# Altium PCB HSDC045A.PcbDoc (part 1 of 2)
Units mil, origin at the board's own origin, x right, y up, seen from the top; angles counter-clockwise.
Board outline 3400 x 2200 mil, 4 copper layers (Top Layer, GND, Power, Bottom Layer), stack 60.6 mil thick; 158 components, 100 nets, 469 pads, 343 vias.
Unrouted connection lines stored in the file: 20.
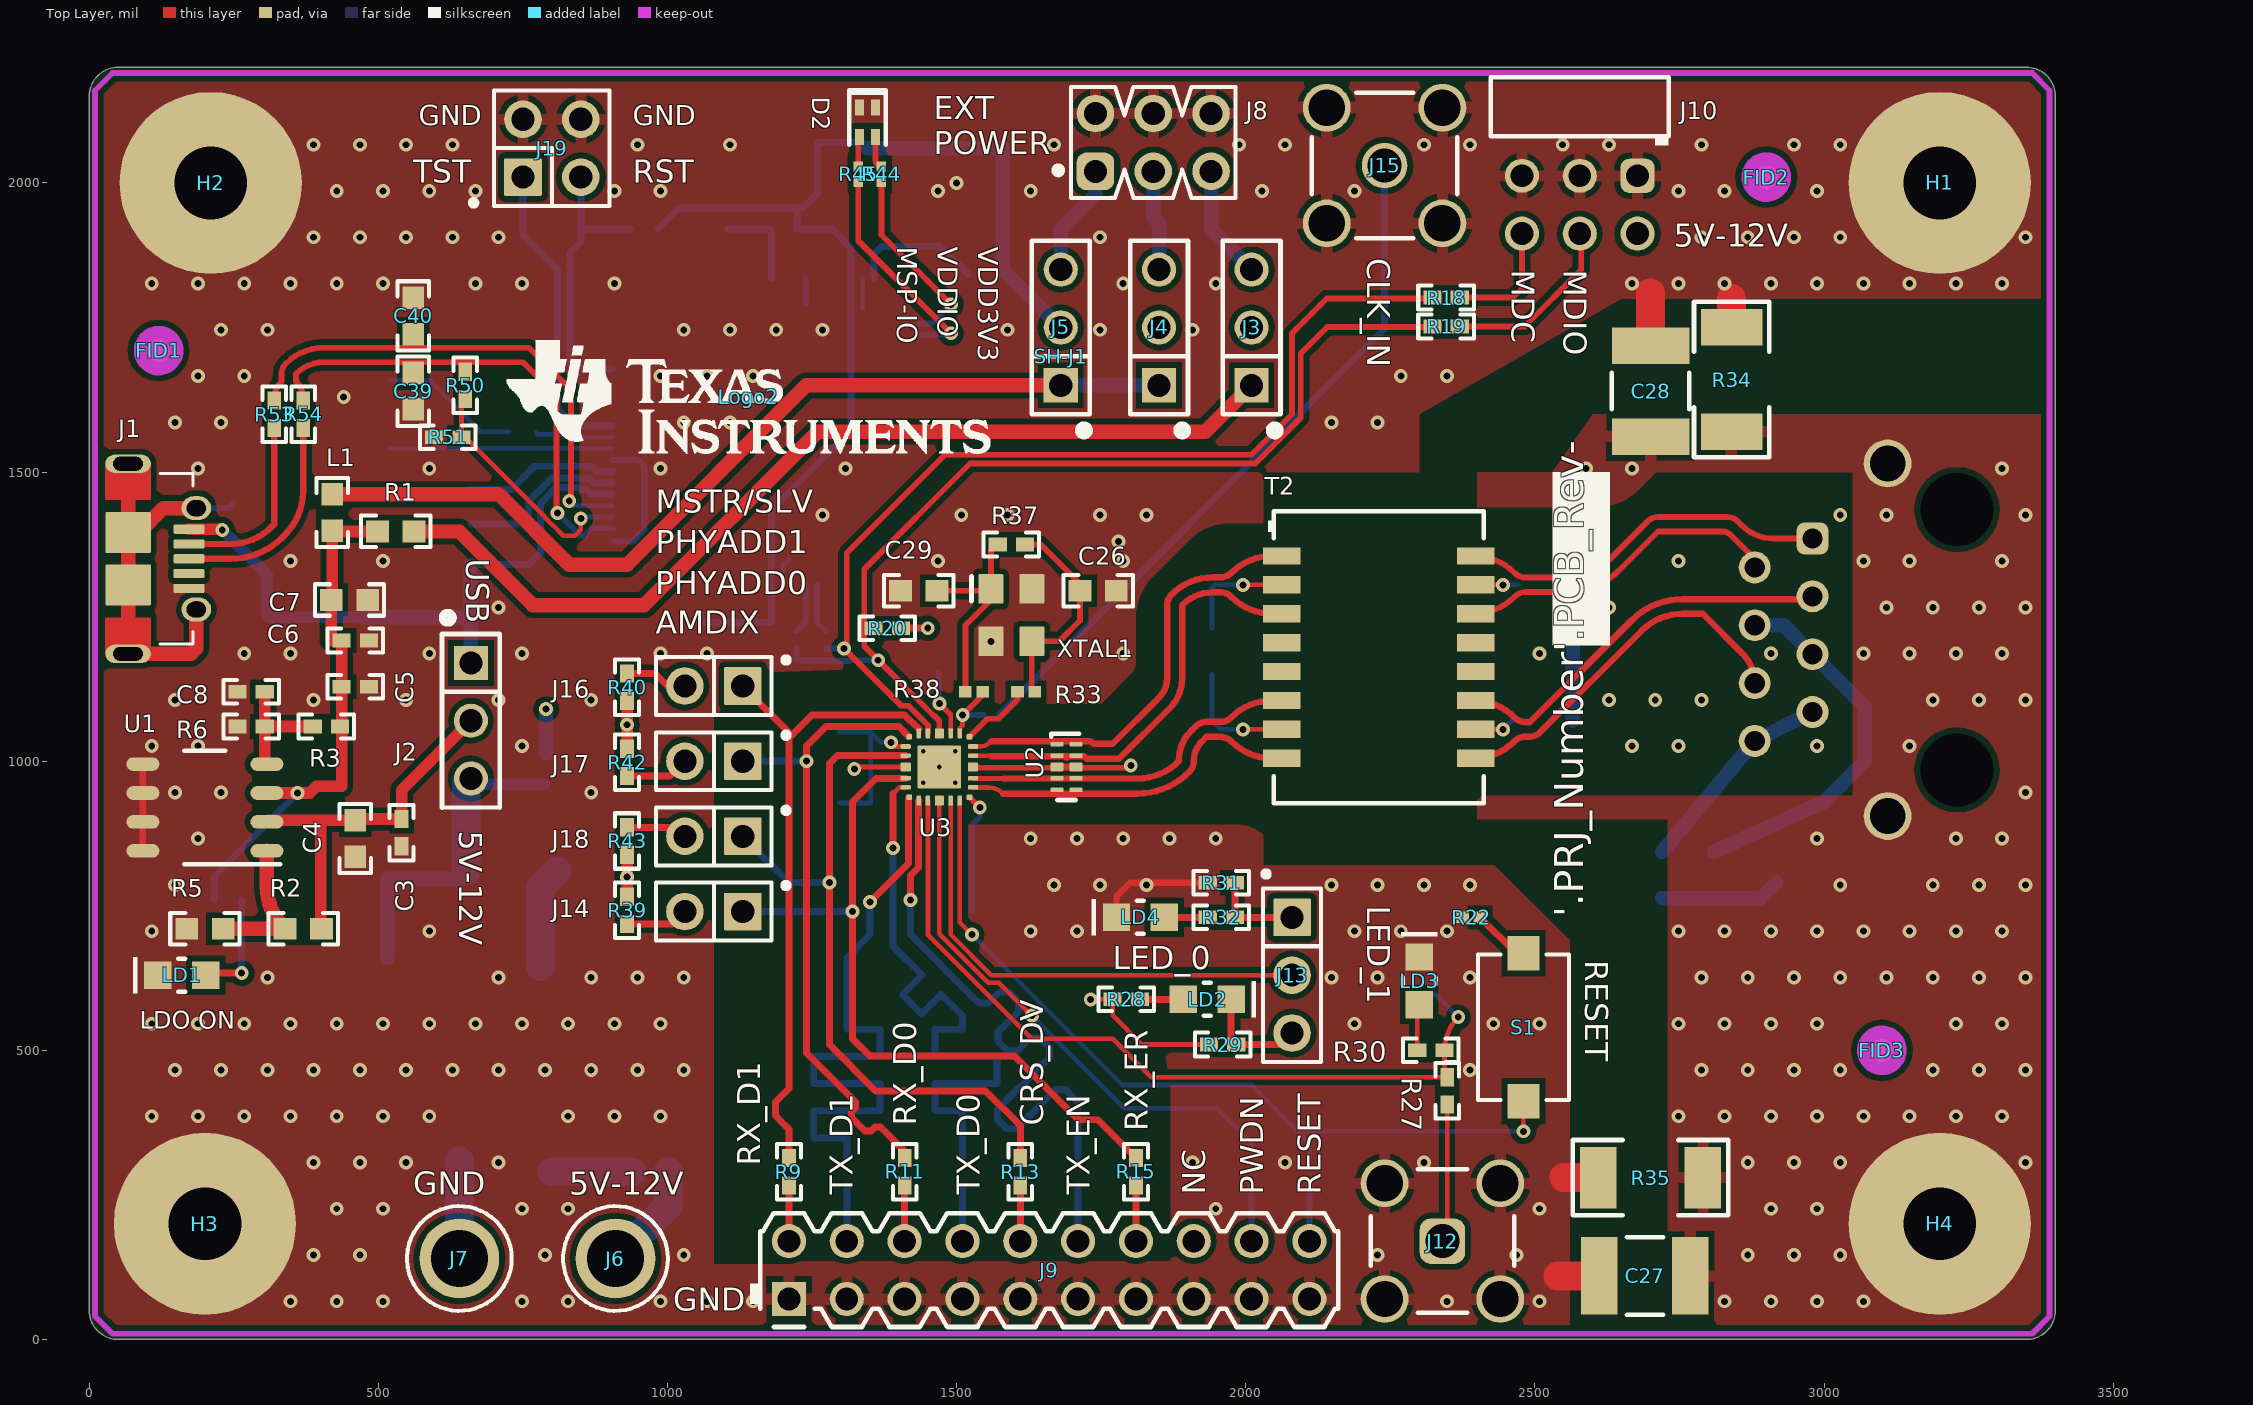
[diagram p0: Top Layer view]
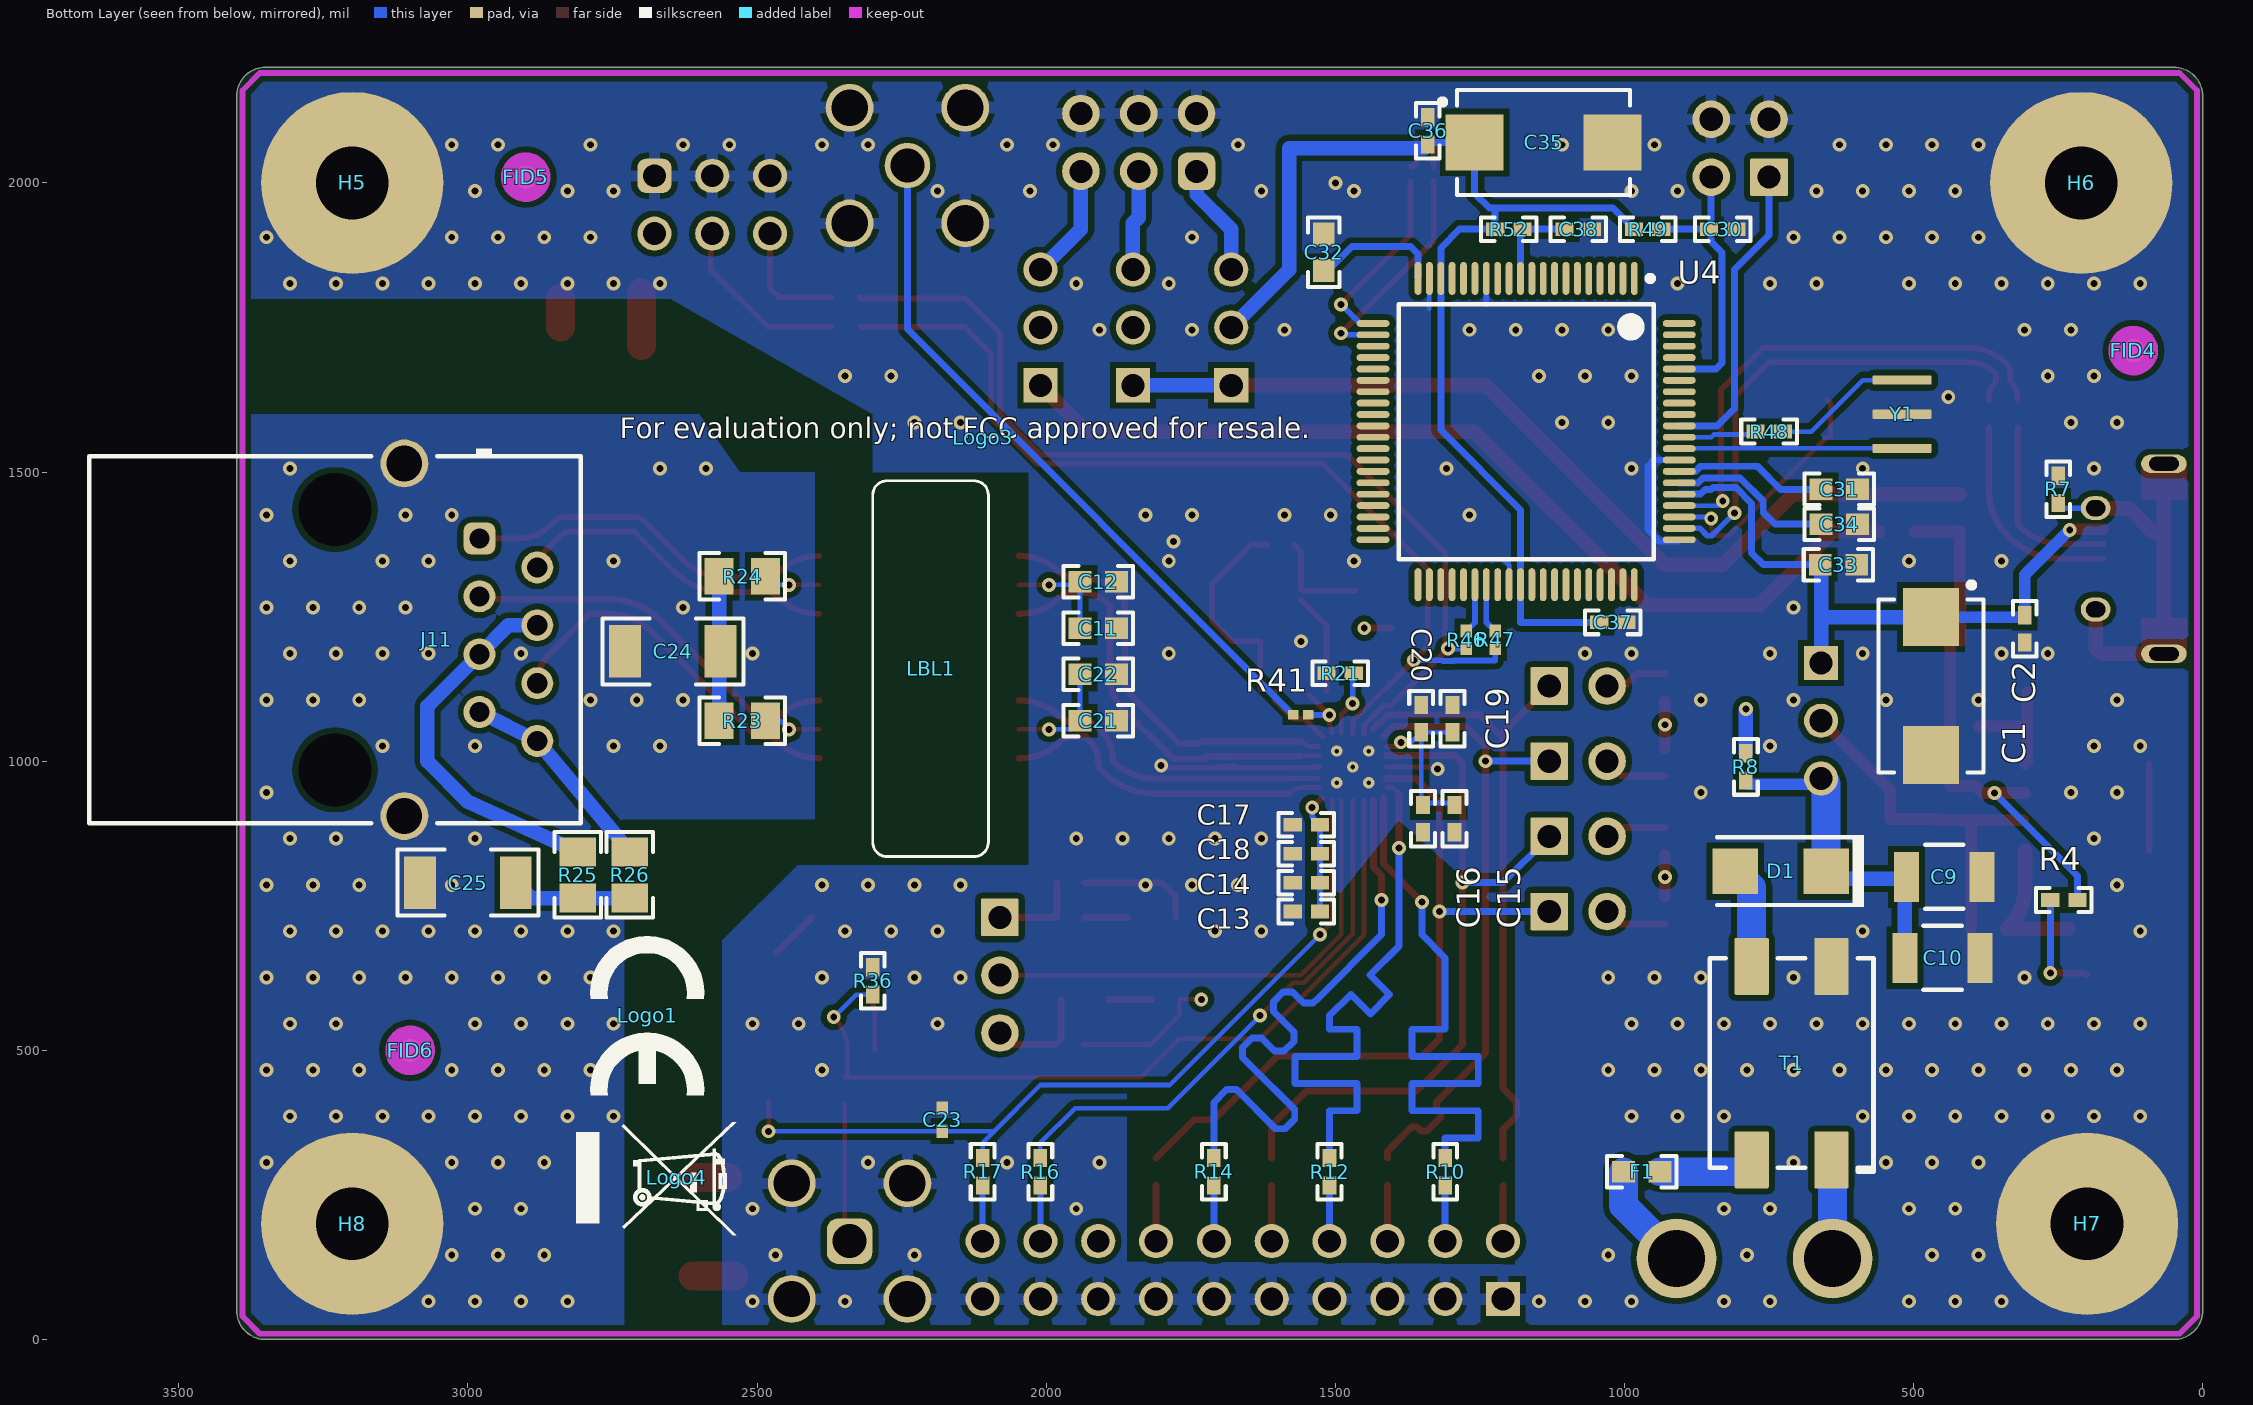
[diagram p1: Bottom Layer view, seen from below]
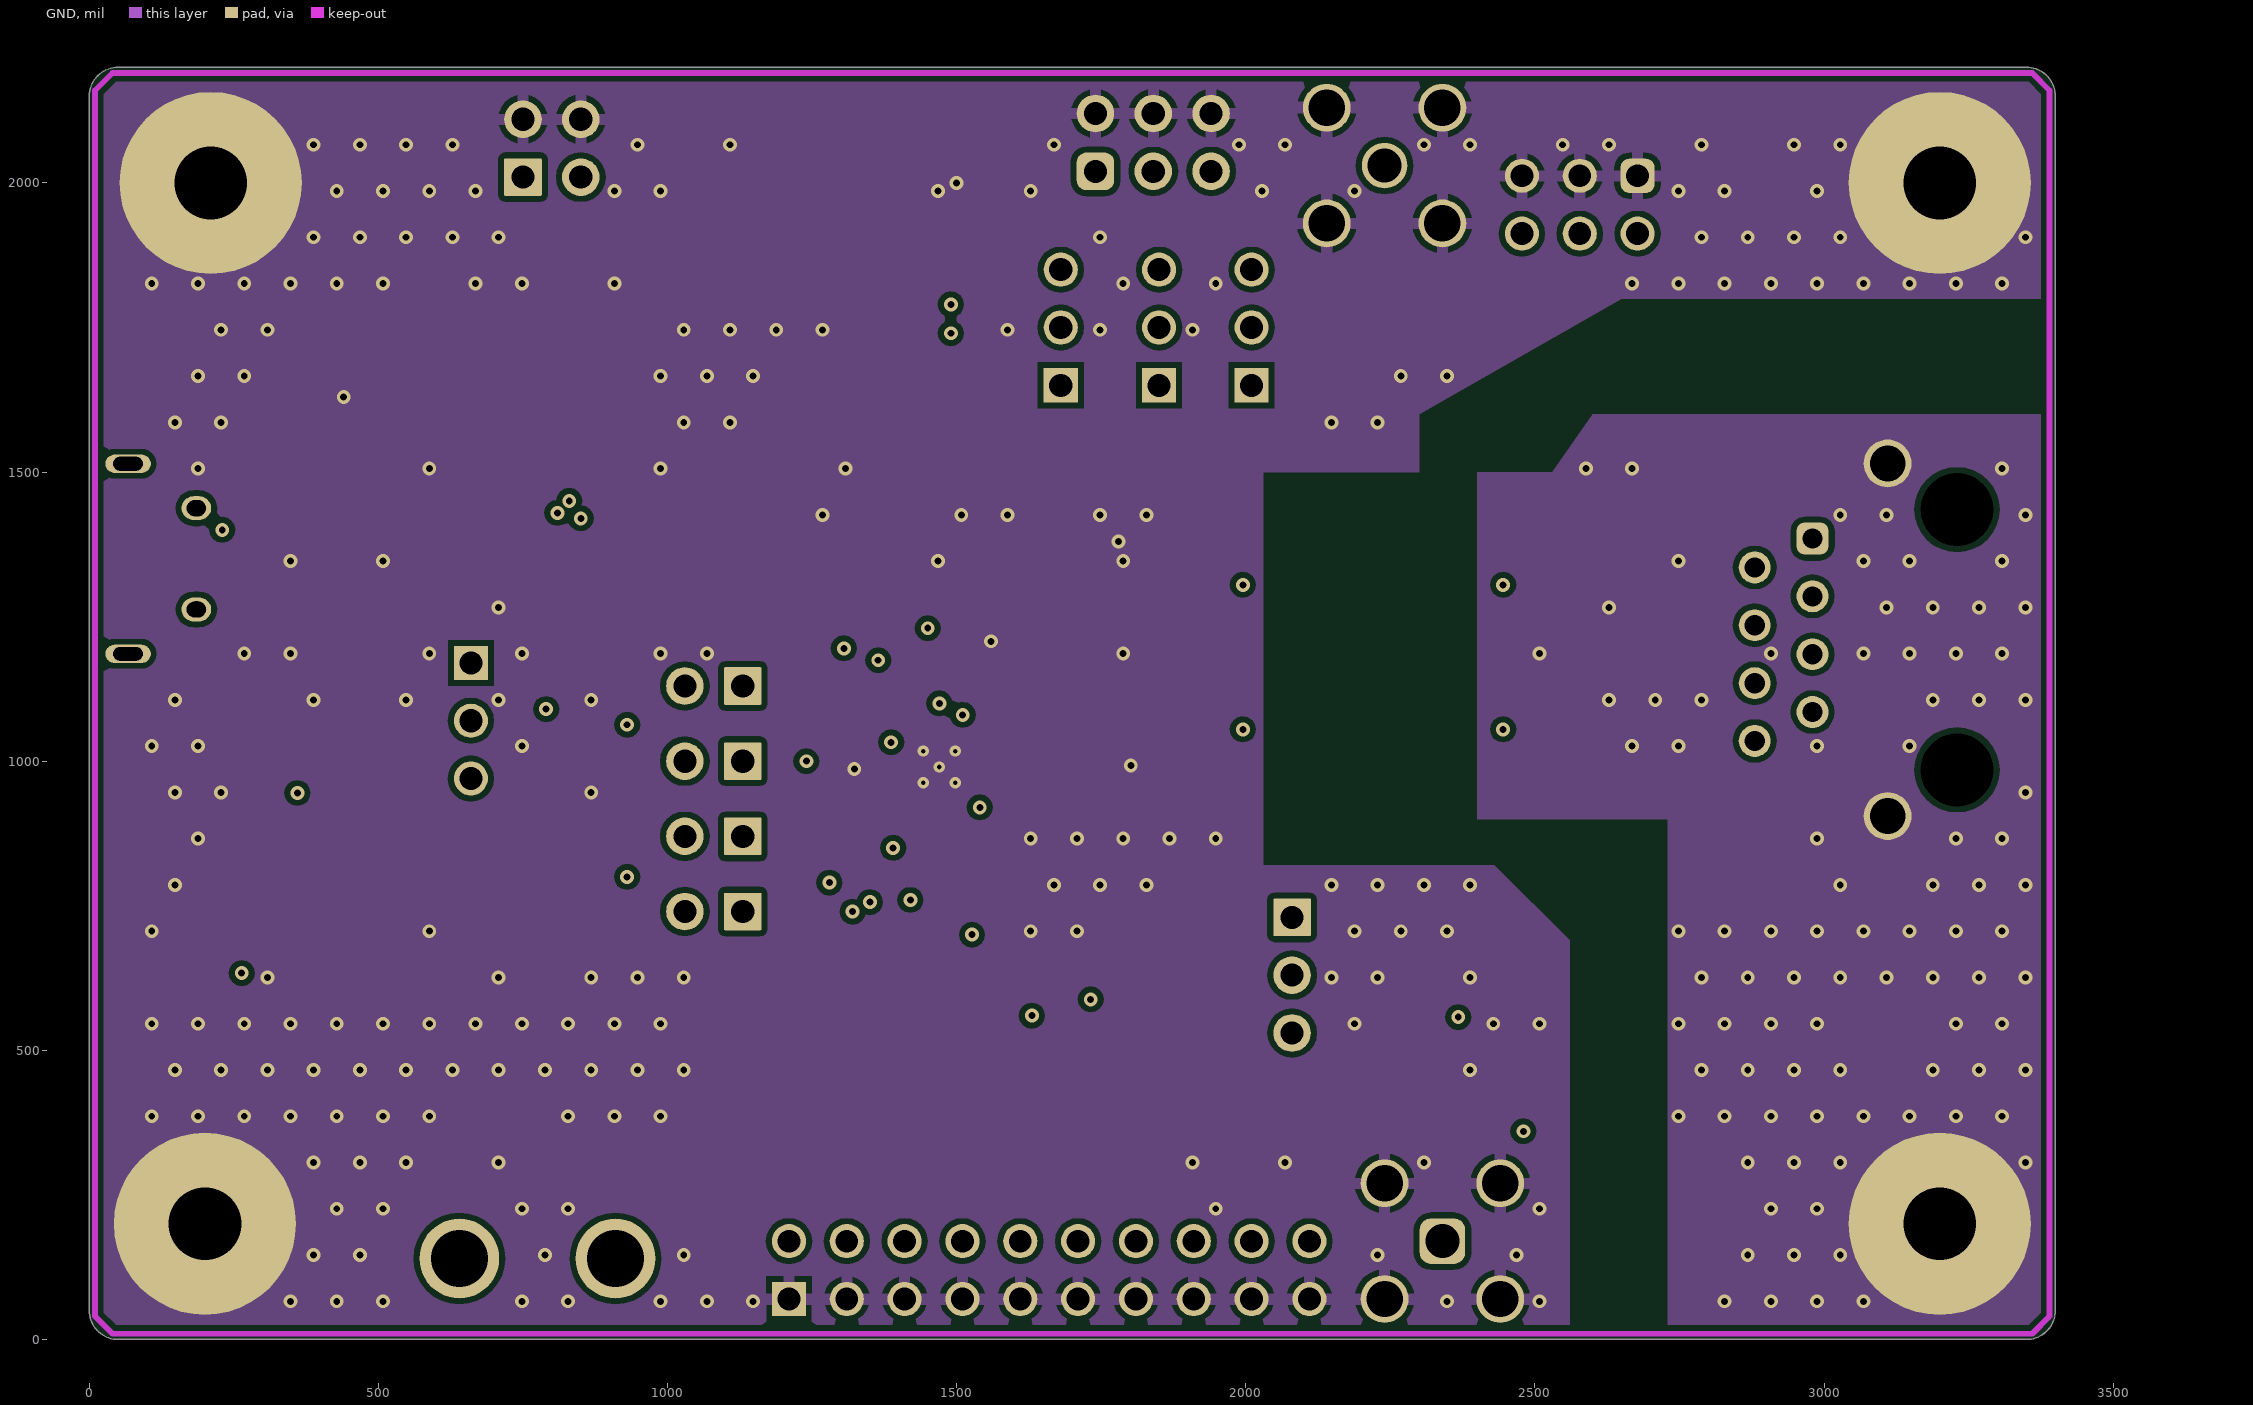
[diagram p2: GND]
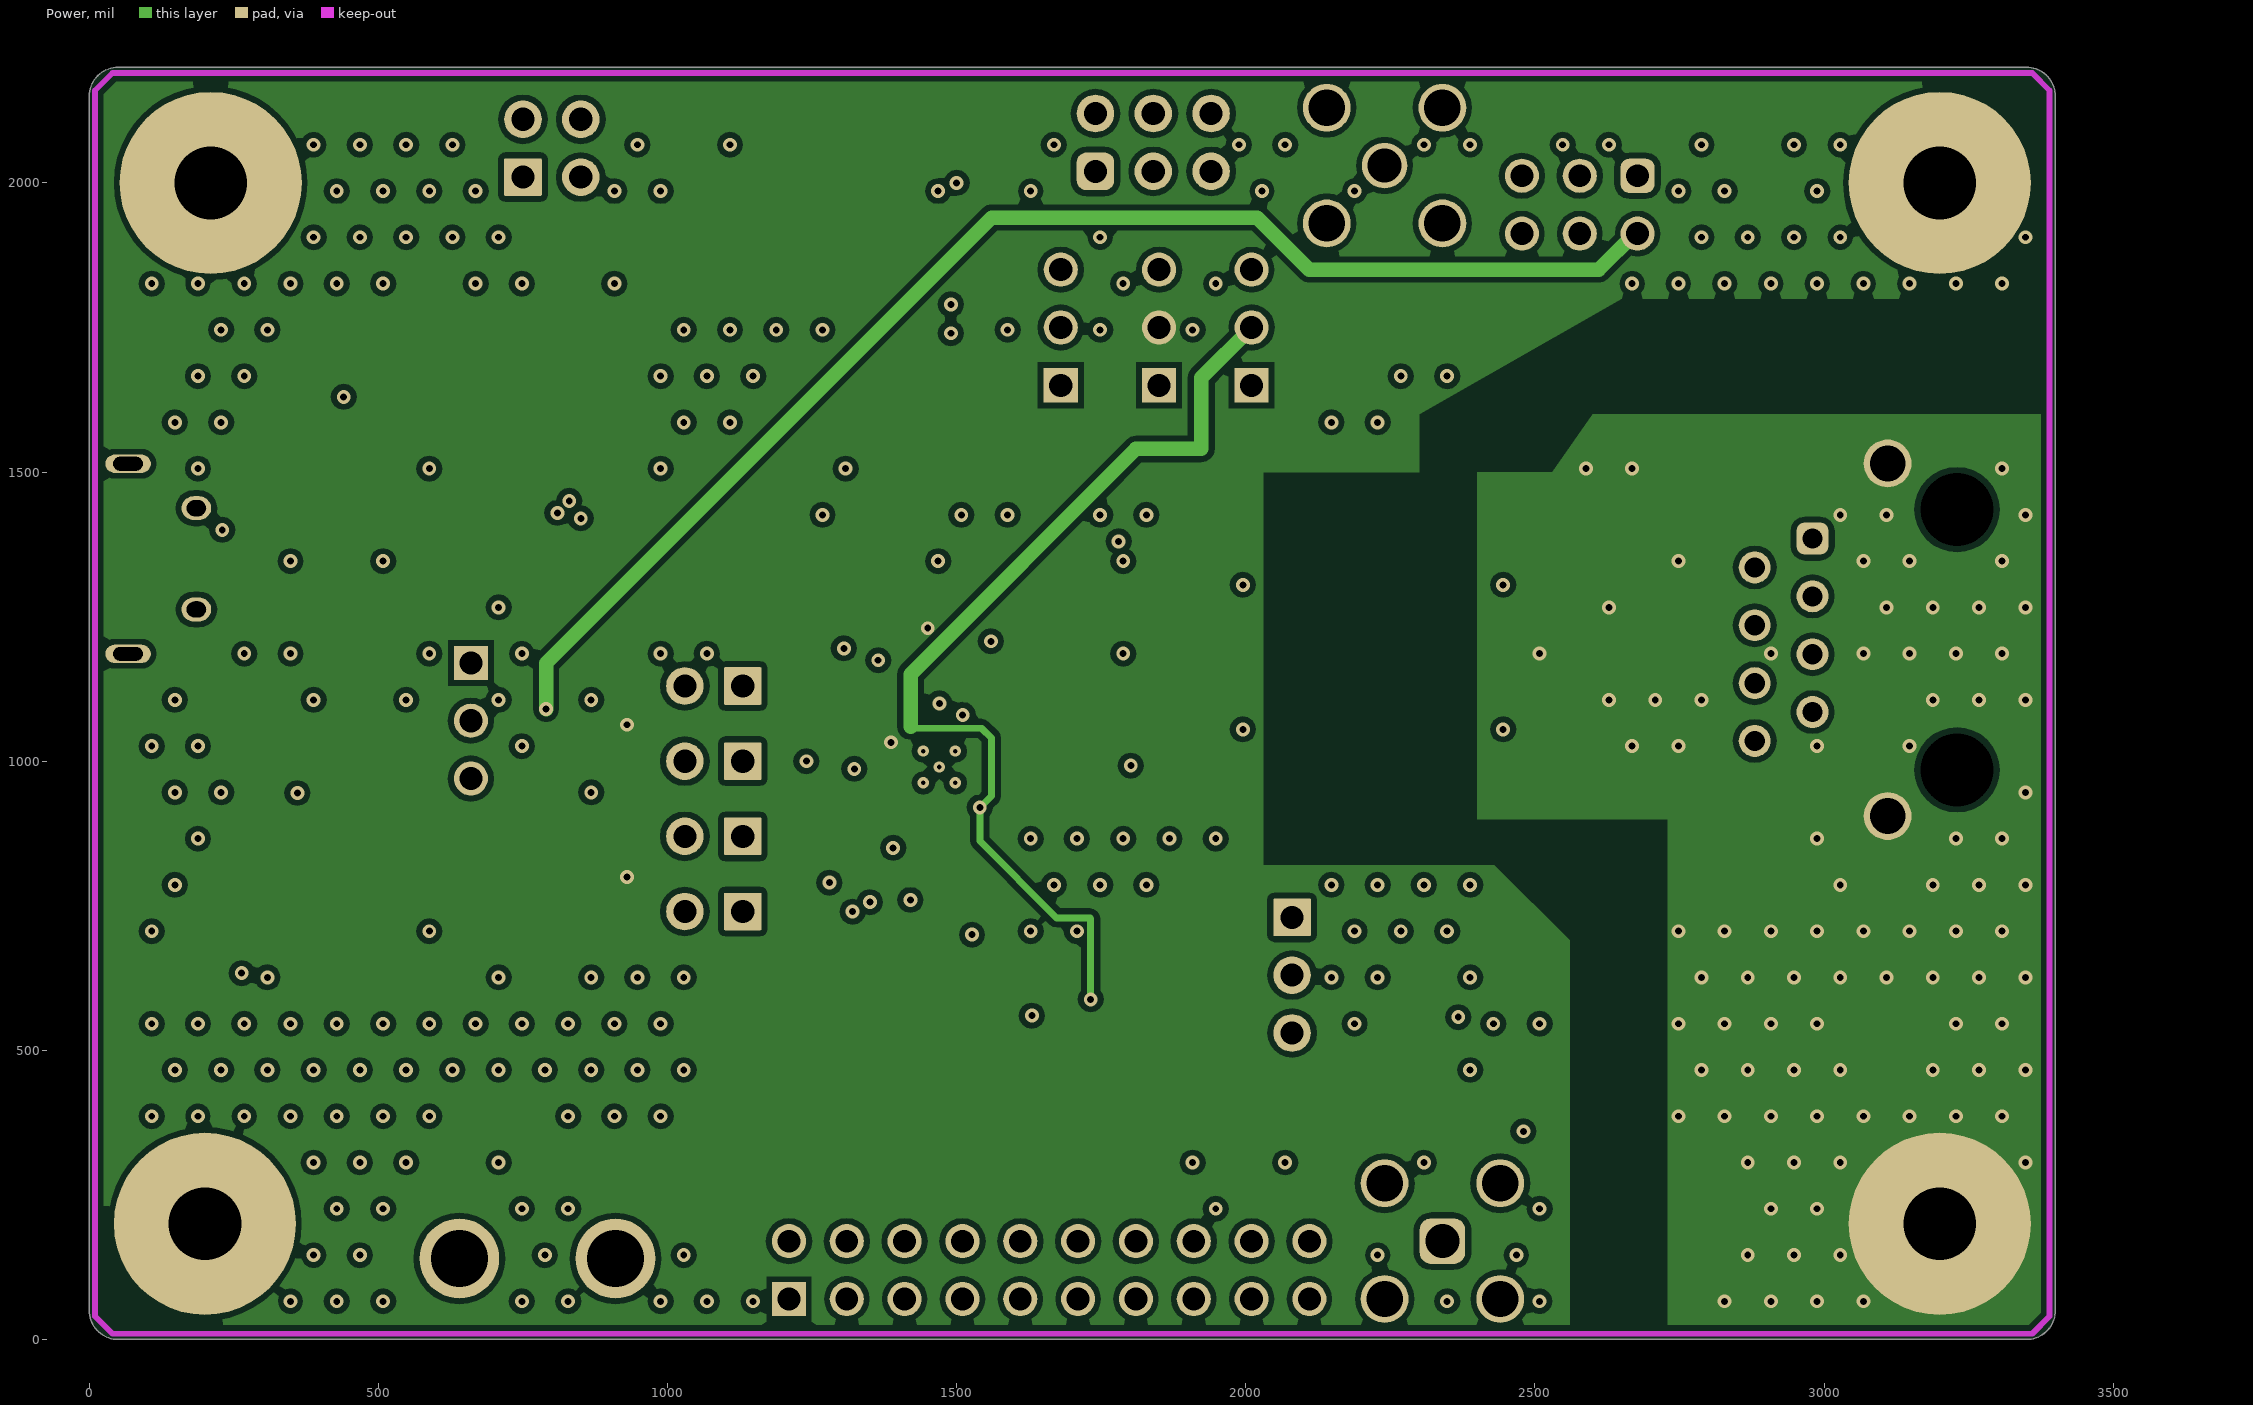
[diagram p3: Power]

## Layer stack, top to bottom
Top Solder: solder mask 0.4, Solder Resist, Dk 3.5
Top Layer: signal copper 1.4
Dielectric 1: prepreg 8, FR-4, Dk 4.6
GND: signal copper 1.4
Dielectric 2: core 39, FR-4, Dk 4.6
Power: signal copper 1.4
Dielectric 3: prepreg 8, FR-4, Dk 4.6
Bottom Layer: signal copper 1.4
Bottom Solder: solder mask 0.4, Solder Resist, Dk 3.5

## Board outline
50,0 3350,0 ccw(c3350,50) 3400,50 3400,2150 ccw(c3350,2150) 3350,2200 50,2200 ccw(c50,2150) 0,2150 0,50 ccw(c50,50)

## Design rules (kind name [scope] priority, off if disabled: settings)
AcuteAngle [All] p1: minimum=4.50000000000000E+0001 checktracksonly=FALSE
AssemblyTestPointUsage [All] p1: valid=2
BoardOutlineClearance BoardOutlineClearance_MountingHoles [OnCopper and InComponentClass('Mounting Holes')] p1: gap=14 ignorepadtopadclearanceinfootprint=FALSE
BoardOutlineClearance BoardOutlineClearance_Poly [OnCopper and IsPoly] p2: gap=14 ignorepadtopadclearanceinfootprint=FALSE
BoardOutlineClearance [OnCopper and Not InComponentClass('Logo') and not InComponentClass('FiducialMark') and not InRegion(1000,500,4000,800) and not InPoly] p3: gap=14 ignorepadtopadclearanceinfootprint=FALSE
Clearance "Stitching GND" [IsStitchingVia and InNet('GND') vs (IsVia and (Not IsStitchingVia)) Or (IsPad and (Not InComponent('U3')))] p1: gap=5 ignorepadtopadclearanceinfootprint=FALSE except(0: Arc-Hole Track-Hole SMDPad-Hole THPad-Hole Via-Hole Fill-Hole Poly-Hole Region-Hole Text-Hole)
Clearance Clearance_Keepouts [((IsTrack Or IsArc) And Not InPoly) And IsFree and IsKeepOut vs ((IsTrack Or IsArc) And Not InPoly) And IsFree and IsKeepOut] p2: gap=0 ignorepadtopadclearanceinfootprint=FALSE
Clearance Clearance_Poly [InPolygon] p3: gap=10 ignorepadtopadclearanceinfootprint=FALSE except(0: Arc-Hole Track-Hole SMDPad-Hole THPad-Hole Via-Hole Fill-Hole Poly-Hole Region-Hole Text-Hole)
Clearance Clearance_FiducialMark [IsKeepOut and InComponentClass('FiducialMark') vs IsPad and InComponentClass('FiducialMark')] p4: gap=0 ignorepadtopadclearanceinfootprint=FALSE
Clearance [All] p5: gap=5 ignorepadtopadclearanceinfootprint=FALSE
ComponentClearance ComponentClearance_MountingHoles_FiducialMarks [InComponentClass('Mounting Holes') vs InComponentClass('FiducialMark')] p1: gap=50 collisioncheckmode=3 verticalgap=10 showdistances=FALSE
ComponentClearance ComponentClearance_Shunt [InComponentClass('Header') vs InComponentClass('Shunt')] p2: gap=0 collisioncheckmode=3 verticalgap=0 showdistances=FALSE
ComponentClearance ComponentClearance_Shunt_1 [InComponentClass('Shunt') vs InComponentClass('Shunt')] p3: gap=0 collisioncheckmode=3 verticalgap=0 showdistances=FALSE
ComponentClearance ComponentClearance_Logo [InComponentClass('Logo')] p4: gap=50 collisioncheckmode=3 verticalgap=10 showdistances=FALSE
ComponentClearance ComponentClearance_ScrewToNut [(HasFootprint('NY PMS 440 0025 PH')) vs (HasFootprint('Keystone_1902C'))] p5: gap=5 collisioncheckmode=3 verticalgap=10 showdistances=FALSE
ComponentClearance ComponentClearance_MountingHoles [InComponentClass('Mounting Holes')] p6: gap=250 collisioncheckmode=3 verticalgap=100000 showdistances=FALSE
ComponentClearance ComponentClearance_SmallPassives [HasFootprint('0201*') or HasFootprint('0402*') or HasFootprint('0508') or HasFootprint('0603*') or HasFootprint('0612') or HasFootprint('0805*') or HasFootprint('0815*') or HasFootprint('0830*') or HasFootprint('1206*') or HasFootprint('1210*') or HasFootprint('1808*') or HasFootprint('1812*') or HasFootprint('1825*') or HasFootprint('2010*') or HasFootprint('2220*') or HasFootprint('2225*') or HasFootprint('2512*') or HasFootprint('2728*') or HasFootprint('3518*') vs HasFootprint('0201*') or HasFootprint('0402*') or HasFootprint('0508') or HasFootprint('0603*') or HasFootprint('0612') or HasFootprint('0805*') or HasFootprint('0815*') or HasFootprint('0830*') or HasFootprint('1206*') or HasFootprint('1210*') or HasFootprint('1808*') or HasFootprint('1812*') or HasFootprint('1825*') or HasFootprint('2010*') or HasFootprint('2220*') or HasFootprint('2225*') or HasFootprint('2512*') or HasFootprint('2728*') or HasFootprint('3518*')] p7: gap=14.96 collisioncheckmode=3 verticalgap=10 showdistances=FALSE
ComponentClearance ComponentClearance_THtoSMT [IsThruComponent vs IsSMTComponent] p8: gap=10 collisioncheckmode=3 verticalgap=30 showdistances=FALSE
ComponentClearance ComponentClearance_THtoTH [IsThruComponent vs IsThruComponent] p9: gap=30 collisioncheckmode=3 verticalgap=30 showdistances=FALSE
ComponentClearance [All] p10: gap=30 collisioncheckmode=3 verticalgap=10 showdistances=FALSE
DiffPairsRouting [All] p1: maxlimit=16 minlimit=3 mostfreqgap=15 toplayer_minwidth=3 toplayer_maxwidth=11 toplayer_prefwidth=9 midlayer1_minwidth=3 midlayer1_maxwidth=11 midlayer1_prefwidth=9 midlayer2_minwidth=3 midlayer2_maxwidth=11 midlayer2_prefwidth=9 bottomlayer_minwidth=3 bottomlayer_maxwidth=11 bottomlayer_prefwidth=9 maxuncoupledlength=1000
FabricationTestPointUsage TestPointUsage [All] p1: valid=2 allowmultiple=FALSE
FabricationTestpoint Testpoint [All] p1: side=3 testpointundercomponent=TRUE minsize=40 maxsize=100 preferedsize=60 minholesize=0 maxholesize=40 preferedholesize=32 testpointgrid=1 allowsidetop=TRUE allowsidebottom=TRUE usegrid=TRUE gridtolerance=0.01
FanoutControl Fanout_LCC [IsLCC] p1: bgadir=Out bgaviamode=Centered fanoutstyle=Auto fanoutdirection=Alternating viagrid=1 // Fanout_LCC (Default Rule)
FanoutControl Fanout_BGA [IsBGA] p2: bgadir=Out bgaviamode=Centered fanoutstyle=Auto fanoutdirection=Alternating viagrid=1 // Fanout_BGA (Default Rule)
FanoutControl Fanout_Default [All] p4: bgadir=Out bgaviamode=Centered fanoutstyle=Auto fanoutdirection=Alternating viagrid=1 // Fanout_Default (Default Rule)
FanoutControl Fanout_Small [(CompPinCount < 5)] p5: bgadir=Out bgaviamode=Centered fanoutstyle=Auto fanoutdirection=OutThenIn viagrid=1 // Fanout_Small (Default Rule)
HoleSize [All] p1: absolutevalues=TRUE maxlimit=300 minlimit=6 maxpercent=80.000 minpercent=20.000
MinimumAnnularRing MinimumAnnularRing_ThermalPadVias [IsVia and InAnyComponent] p1: minimumring=5.91
MinimumAnnularRing MinimumAnnularRing_J1 [InNet('NetJ1_6')] p2: minimumring=2
MinimumAnnularRing [All] p3: minimumring=5
MinimumSolderMaskSliver MinimumSolderMaskSliver_Logo [InComponentClass('Logo') vs InComponentClass('Logo')] p1: minsoldermaskwidth=0.7
MinimumSolderMaskSliver [All] p2: minsoldermaskwidth=3.94
PlaneConnect [All] p1: planeconnectstyle=Direct reliefexpansion=10 reliefentries=4 reliefconductorwidth=10 reliefairgap=10
PolygonConnect PolygonConnect_ThermalRelief [InComponent('J9') or InComponent('J12')or InComponent('J15')or InComponent('R34')or InComponent('C28')or InComponent('R35')or InComponent('C27')or InComponent('J8')or InComponent('J10') or InComponent('J19') vs InNet('GND')or InNet('EARTH_GND')] p1: connectstyle=Relief reliefconductorwidth=20 reliefentries=4 polygonreliefangle="90 Angle" airgapwidth=10
PolygonConnect [All] p2: connectstyle=Direct reliefconductorwidth=20 reliefentries=4 polygonreliefangle="90 Angle" airgapwidth=10
RoutingVias ThermalPadVias [IsVia and InAnyComponent] p1: holewidth=7.87 width=19.68 viastyle="Through Hole" minholewidth=7.87 minwidth=19.68 maxholewidth=12.99 maxwidth=23.62
RoutingVias [All] p2: holewidth=12 width=24 viastyle="Through Hole" minholewidth=6 minwidth=12 maxholewidth=40 maxwidth=65
SilkToBoardRegionClearance [Not ((IsComment or IsDesignator) And (Hide <> 'False')) and not InRegion(1000,500,4000,800)] p1:
SilkToSilkClearance SilkToSilkClearance_Pb-FreeLogo [(HasFootprint('Pb-Free_Overlay_Medium') OR HasFootprint('Pb-Free_Overlay_Small')) vs (HasFootprint('Pb-Free_Overlay_Medium') OR HasFootprint('Pb-Free_Overlay_Small'))] p1: silktosilkclearance=0
SilkToSilkClearance [All] p2: silktosilkclearance=4
SilkToSolderMaskClearance SilkToComponentPadClearance [IsPad and InAnycomponent] p1: minsilkscreentomaskgap=4 clearancetoexposedcopper=TRUE
SilkToSolderMaskClearance "Silk to Solder Mask Opening" [All] p2: minsilkscreentomaskgap=4 clearancetoexposedcopper=FALSE
SolderMaskExpansion [All] p1: expansion=1.97
Width Width_U3Pad [IsComponent = 'U3'] p1: maxlimit=50 minlimit=7 preferedwidth=12
Width [All] p2: maxlimit=100 minlimit=7 preferedwidth=12 checkconnectedcopper=TRUE
15 further rules are at their usual default settings.

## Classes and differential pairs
component class "Mounting Holes": H1 H2 H3 H4
component class Logo: Logo2
component class HSDC045A_Hardware: FID1 FID2 FID3 FID4 FID5 FID6 H1 H2 H3 H4 H5 H6 H7 H8 LBL1 Logo1 Logo2 Logo3 Logo4 SH-J1 SH-J2 SH-J3 SH-J4 SH-J5 ZZ1 ZZ2 ZZ3 ZZ4
component class FiducialMark: FID1 FID2 FID3 FID4 FID5 FID6
component class AssemblyNote: ZZ1 ZZ2 ZZ3 ZZ4
component class Label: LBL1
component class Header: J2 J3 J4 J5 J8 J9 J10 J13 J14 J16 J17 J18 J19 J22
component class HSDC045A_Coms: C30 C31 C32 C33 C34 C35 C36 C37 C38 C39 C40 D2 J19 R44 R45 R46 R47 R48 R49 R50 R51 R52 R53 R54 R56 U4 Y1
component class HSDC045A_DP83825: C11 C12 C13 C14 C15 C16 C17 C18 C19 C20 C21 C22 C23 C24 C25 C26 C27 C28 C29 J9 J10 J11 J12 J13 J14 J15 J16 J17 J18 LD2 LD3 LD4 R9 R10 R11 R12 R13 R14 R15 R16 R17 R18 R19 R20 R21 R22 R23 R24 R25 R26 R27 R28 R29 R30 R31 R32 R33 R34 R35 R36 R37 R38 R39 R40 R41 R42 R43 S1 T2 U2 U3 XTAL1
component class HSDC045A_Power: C1 C2 C3 C4 C5 C6 C7 C8 C9 C10 D1 F1 J1 J2 J3 J4 J5 J6 J7 J8 L1 LD1 R1 R2 R3 R4 R5 R6 R7 R8 T1 U1
differential pair RD: +RD_P -RD_N
differential pair TARGET_D: +TARGET_D_P -TARGET_D_N
differential pair TD_CH1: +TD_CH1_P -TD_CH1_N
differential pair TD_CH2: +TD_CH2_P -TD_CH2_N
differential pair TD: +TD_P -TD_N
differential pair USB: +USB_P -USB_N

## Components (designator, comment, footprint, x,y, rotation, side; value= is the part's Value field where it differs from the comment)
C1 "293D475X9035D2TE3" 7343-31 470,1130 r270 bottom value=4.7uF
C2 "GRM155R71C104KA88D" 0402 307.6,1228.82 r90 bottom value=0.1uF
C3 "GRM155R6YA105ME11D" 0402 540,876.38 r270 top value=1uF
C4 "GRM188R6YA106MA73" 0603 460,866.38 r270 top value=10uF
C5 "GRM155C81C225KE11D" 0402 460,1128.7 r0 top value=2.2uF
C6 "GRM155C81C225KE11D" 0402 460,1208.7 r0 top value=2.2uF
C7 "GRM188R6YA106MA73" 0603 450,1278.7 r0 top value=10uF
C8 "GRM1555C1E471JA01D" 0402 280,1120 r180 top value=470pF
C9 "CGA6P1X7R1C226M250AC" 1210_280 447.01,800 r180 bottom value=22uF
C10 "CGA6P1X7R1E106M250AC" 1210_280 450,660 r180 bottom value=10uF
C11 "C0603C104K8RACTU" 0603 1910,1230.06 r180 bottom value=0.1uF
C12 "C0603C104K8RACTU" 0603 1910,1310.09 r180 bottom value=0.1uF
C13 "C1005X5R1A104K050BA" 0402 1550,740 r0 bottom value=0.1uF
C14 "GRM155R60J106ME11" 0402 1550,790 r0 bottom value=10uF
C15 "C1005X5R1A104K050BA" 0402 1293.95,900.79 r270 bottom value=0.1uF
C16 "GRM155R60J106ME11" 0402 1348.35,900.79 r270 bottom value=10uF
C17 "GRM155R61A105KE15D" 0402 1550,890 r0 bottom value=1uF
C18 "GRM155R61A105KE15D" 0402 1550,840 r0 bottom value=1uF
C19 "GRM155R61A105KE15D" 0402 1297.26,1073.62 r90 bottom value=1uF
C20 "GRM155R61A105KE15D" 0402 1351.65,1073.62 r90 bottom value=1uF
C21 "C0603C104K8RACTU" 0603 1910,1070 r180 bottom value=0.1uF
C22 "C0603C104K8RACTU" 0603 1910,1150.03 r180 bottom value=0.1uF
C23 "GRM155R71H103KA88D" 0402L 2180,380 r270 bottom value=0.01uF
C24 "GR442QR73D102KW01L" 1808 2645.59,1190 r0 bottom value=1000pF
C25 "GR442QR73D102KW01L" 1808 3000,790 r0 bottom value=1000pF
C26 "CGA3E2C0G1H220J080AA" 0603 1744.57,1294.66 r0 top value=22pF
C27 "1812GC472KAT1A" 1812_254 2690,110 r0 top value=4700pF
C28 "1812GC472KAT1A" 1812_254 2700,1640 r270 top value=4700pF
C29 "CGA3E2C0G1H220J080AA" 0603 1434.57,1294.72 r180 top value=22pF
C30 "C1005NP01H102J050BA" 0402 830,1920 r0 bottom value=1000pF
C31 "C1608X5R1H224K080AB" 0603 628.5,1470 r180 bottom value=0.22uF
C32 "C1608X6S1H474K080AB" 0603 1520,1880 r90 bottom value=0.47uF
C33 "C1608X5R1V475K080AC" 0603 630,1340 r0 bottom value=4.7uF
C34 "C1608X5R1H224K080AB" 0603 628.5,1410 r180 bottom value=0.22uF
C35 "TPSD106K035R0125" 7343-31 1140,2070 r180 bottom value=10uF
C36 "GRM155R71C104KA88D" 0402 1340,2090 r270 bottom value=0.1uF
C37 "GRM155R71C104KA88D" 0402 1020,1240 r0 bottom value=0.1uF
C38 "GRM155R71C104KA88D" 0402 1080,1920 r0 bottom value=0.1uF
C39 "CGA3E2NP01H100D080AA" 0603 560,1640 r90 top value=10pF
C40 "CGA3E2NP01H100D080AA" 0603 560,1770 r270 top value=10pF
D1 "NRVBA160T3G" SMA 730,810 r0 bottom value=60V
D2 "HSMF-C165" HSMF-C165_RG 1346.06,2105.15 r90 top value=Rg
F1 "F0603E3R00FSTR" 0603 970,290 r180 bottom
FID1 "Fiducial" Fiducial10-20 120,1710 r0 top
FID2 "Fiducial" Fiducial10-20 2900,2010 r0 top
FID3 "Fiducial" Fiducial10-20 3100,500 r0 top
FID4 "Fiducial" Fiducial10-20 120,1710 r180 bottom
FID5 "Fiducial" Fiducial10-20 2900,2010 r180 bottom
FID6 "Fiducial" Fiducial10-20 3100,500 r180 bottom
H1 "NY PMS 440 0025 PH" "NY PMS 440 0025 PH" 3200,2000 r0 top locked
H2 "NY PMS 440 0025 PH" "NY PMS 440 0025 PH" 210,2000 r0 top locked
H3 "NY PMS 440 0025 PH" "NY PMS 440 0025 PH" 200,200 r0 top locked
H4 "NY PMS 440 0025 PH" "NY PMS 440 0025 PH" 3200,200 r0 top locked
H5 "1902C" Keystone_1902C 3200,2000 r180 bottom locked
H6 "1902C" Keystone_1902C 210,2000 r180 bottom locked
H7 "1902C" Keystone_1902C 200,200 r180 bottom locked
H8 "1902C" Keystone_1902C 3200,200 r180 bottom locked
J1 "475890001" Molex_0475890001 10,1350 r270 top
J2 "PEC03SAAN" CONN_PEC03SAAN 660,1070 r270 top
J3 "PEC03SAAN" CONN_PEC03SAAN 2010,1750 r90 top
J4 "PEC03SAAN" CONN_PEC03SAAN 1850,1750 r90 top
J5 "PEC03SAAN" CONN_PEC03SAAN 1680,1750 r90 top
J6 "1502-2" Keystone1502-2 910,140 r270 top
J7 "1502-2" Keystone1502-2 640,140 r270 top
J8 "5-146254-3" TE_5-146254-3 1840,2070 r0 top
J9 "PRPC010DAAN-RC" Sullins_xxxC010DAAN 1660,120 r90 top
J10 "90122-0763" Molex_90122-0763 2577.5,1962.31 r270 top
J11 "SS-7188S-A-NF" Stewart_SS-7188S-A-NF 3230,1210 r270 bottom
J12 "5-1814400-1" TE_5-1814400-1 2340,170 r90 top
J13 "HTSW-103-07-G-S" Samtec_HTSW-103-07-G-S 2080,630 r270 top
J14 "HTSW-102-07-G-S" Samtec_HTSW-102-07-G-S 1080,740 r180 top
J15 "5-1814832-1" TE_5-1814832-1 2240,2030 r270 top
J16 "HTSW-102-07-G-S" Samtec_HTSW-102-07-G-S 1080,1130 r180 top
J17 "HTSW-102-07-G-S" Samtec_HTSW-102-07-G-S 1080,1000 r180 top
J18 "HTSW-102-07-G-S" Samtec_HTSW-102-07-G-S 1080,870 r180 top
J19 "TSW-102-07-G-D" TSW-102-07-G-D 800,2060 r0 top
L1 "BLM18AG102SN1D" 0603 420,1430 r90 top value="1000 ohm"
LBL1 "THT-14-423-10" Label_650x200 2200,1160 r270 bottom
LD1 "QTLP630C4TR" QTLP630C_Green 160,630 r180 top value=Green
LD2 "QTLP630C4TR" QTLP630C_Green 1933.33,588.22 r0 top value=Green
LD3 "QTLP630C4TR" QTLP630C_Green 2300,620 r90 top value=Green
LD4 "QTLP630C4TR" QTLP630C_Green 1817.72,730 r180 top value=Green
Logo1 "CE Mark" CE_Mark_5mm 2690,560 r270 bottom
Logo2 "Texas Instruments" TI_Stacked_Overlay_Small 1140,1630 r0 top
Logo3 "FCC disclaimer" FCC_disclaimer 2110,1560 r180 bottom
Logo4 "WEEE logo" WEEE_Minimum 2640,280 r270 bottom
R1 "ERJ-3GEY0R00V" 0603 530,1397.22 r0 top value=0
R2 "ERJ-3GEY0R00V" 0603 370,710 r0 top value=0
R3 "CRCW0402100KDHEDP" 0402 410,1060 r0 top value=100k
R4 "CRCW0402470RJNED" 0402 240,760 r180 bottom value=470
R5 "ERJ-3GEY0R00V" 0603 200,710 r0 top value=0
R6 "CRCW0402165KFKED" 0402 280,1060 r0 top value=165k
R7 "CRCW040233R0JNED" 0402 250,1470 r90 bottom value=33
R8 "MCR01MZPJ000" 0402 790,990 r270 bottom value=0
R9 "CRCW04020000Z0ED" 0402 1210,290 r90 top value=0
R10 "CRCW04020000Z0ED" 0402 1310,290 r90 bottom value=0
R11 "CRCW04020000Z0ED" 0402 1410,290 r90 top value=0
R12 "CRCW04020000Z0ED" 0402 1510,290 r90 bottom value=0
R13 "CRCW04020000Z0ED" 0402 1610,290 r90 top value=0
R14 "CRCW04020000Z0ED" 0402 1710,290 r90 bottom value=0
R15 "CRCW04020000Z0ED" 0402 1810,290 r90 top value=0
R16 "CRCW04020000Z0ED" 0402 2010,290 r90 bottom value=0
R17 "CRCW04020000Z0ED" 0402 2110,290 r90 bottom value=0
R18 "CRCW04020000Z0ED" 0402 2346.22,1801.81 r0 top value=0
R19 "CRCW04020000Z0ED" 0402 2346.22,1751.81 r0 top value=0
R20 "CRCW04022K20JNED" 0402 1380,1230 r0 top value=2.2k
R21 "CRCW04026K49FKED" 0402 1491.81,1152.13 r0 bottom value=6.49k
R22 "CRCW02012K20JNED" 0201M 2390,730 r0 top value=2.2k
R23 "CRCW080575R0FKEA" 0805_HV 2525.59,1070 r180 bottom value=75.0
R24 "CRCW080575R0FKEA" 0805_HV 2525.59,1320 r180 bottom value=75.0
R25 "CRCW080575R0FKEA" 0805_HV 2810,803.31 r90 bottom value=75.0
R26 "CRCW080575R0FKEA" 0805_HV 2720,803.31 r90 bottom value=75.0
R27 "CRCW04020000Z0ED" 0402 2348.19,430 r270 top value=0
R28 "CRCW0402470RJNED" 0402 1793.32,588.22 r180 top value=470
R29 "CRCW04022K49FKED" 0402 1960,510 r180 top value=2.49k
R30 "CRCW0402470RJNED" 0402 2320,500 r180 top value=470
R31 "CRCW04022K49FKED" 0402 1957.72,790 r0 top value=2.49k
R32 "CRCW0402470RJNED" 0402 1957.72,730 r180 top value=470
R33 "ERJ-1GE0R00C" 0201M 1620,1120 r180 top value=0
R34 "HVCB2010FKC1M00" 2010 2840,1660 r90 top value=1.00Meg
R35 "HVCB2010FKC1M00" 2010 2700,280 r180 top value=1.00Meg
R36 "CRCW04022K49FKED" 0402 2300,620 r90 bottom value=2.49k
R37 "RC0402FR-071ML" 0402 1594.57,1374.72 r0 top value=1.00Meg
R38 "ERJ-1GE0R00C" 0201M 1530,1120 r0 top value=0
R39 "CRCW04022K49FKED" 0402 930,742 r90 top value=2.49k
R40 "CRCW04022K49FKED" 0402 930,1128 r270 top value=2.49k
R41 "ERJ-1GE0R00C" 0201 1560,1080 r180 bottom value=0
R42 "CRCW04022K49FKED" 0402 930,998 r90 top value=2.49k
R43 "CRCW04022K49FKED" 0402 930,862 r270 top value=2.49k
R44 "RC0201JR-07470RL" 0201 1369.84,2015.31 r270 top value=470
R45 "RC0201JR-07470RL" 0201 1329.84,2015.31 r270 top value=470
R46 "ERJ-1GE0R00C" 0201M 1273.5,1210 r90 bottom value=0
R47 "ERJ-1GE0R00C" 0201M 1223.5,1210 r90 bottom value=0
R48 "CRCW04020000Z0ED" 0402 750,1570 r0 bottom value=0
R49 "CRCW040247K0JNED" 0402 960,1920 r180 bottom value=47k
R50 "CRCW04021K40FKED" 0402 650,1650 r90 top value=1.40k
R51 "CRCW04021M00FKED" 0402 620,1560 r180 top value=1.00Meg
R52 "CRCW04020000Z0ED" 0402 1200,1920 r180 bottom value=0
R53 "CRCW040227R0JNED" 0402 320,1600 r270 top value=27
R54 "CRCW040227R0JNED" 0402 370,1600 r270 top value=27
S1 "KSR221GLFS" KSR 2480,540 r270 top
SH-J1 "M7582-05" Harwin_M7582-05 1680,1700 r90 top
SH-J2 "M7582-05" Harwin_M7582-05 3810,180 r90 top
SH-J3 "M7582-05" Harwin_M7582-05 3988,166 r90 top
SH-J4 "M7582-05" Harwin_M7582-05 4238,166 r90 top
SH-J5 "M7582-05" Harwin_M7582-05 4498,166 r90 top
T1 "ACM9070-701-2PL-TL01" TDK_ACM9070 711.11,477.8 r90 bottom
T2 "HX1198FNLT" Pulse_HX1198FNLT 2230,1180 r0 top value=350uH
U1 "TL5209DR" D0008A_N 200,920 r180 top
U2 "TPD4E05U06DQAR" DQA0010A 1690,990 r0 top
U3 "DP83825IRMQR" RMQ0024A 1470,990 r90 top
U4 "MSP430F5529IPN" PN0080A_N 1170,1570 r270 bottom locked
XTAL1 "ECS-250-12-33Q-JES-TR" ECS_ECS-33Q 1594.57,1252.59 r0 top
Y1 "CSTCR4M00G15L99-R0" Murata_CSTCR_G15L 520,1600 r270 bottom
ZZ1 "This Assembly Note is for PCB labels only" AssemblyNoteLabel 2810,6090 r0 top
ZZ2 "These assemblies are ESD sensitive, ESD precautions shall be observed." AssemblyNote 2810,5850 r0 top
ZZ3 "These assemblies must be clean and free from flux and all contaminants. Use of no clean flux is not acceptable." AssemblyNote 2810,5600 r0 top
ZZ4 "These assemblies must comply with workmanship standards IPC-A-610 Class 2, unless otherwise specified." AssemblyNote 2810,5380 r0 top

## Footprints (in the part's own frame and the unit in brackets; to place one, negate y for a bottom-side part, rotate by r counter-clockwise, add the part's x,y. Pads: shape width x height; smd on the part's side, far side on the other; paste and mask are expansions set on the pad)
0201 [mm] "Data from Kemet datasheet CC101_COM dated 7/28/11"
  rect 0.46x0.42 smd mask+0.048: 1(-0.33,0) 2(0.33,0)
  body extent -0.31,-0.16 0.31,0.16, height 0.26
0201M [mm] "Data from Kemet datasheet CC101_COM dated 7/28/11"
  rect 0.56x0.52 smd mask+0.048: 1(-0.38,0) 2(0.38,0)
  body extent -0.31,-0.16 0.31,0.16, height 0.26
0402 [mm] "0402 from SM-752 data"
  rect 0.8x0.6 smd: 1(-0.6,0) 2(0.6,0)
  silkscreen extent -1.22,-0.52 1.22,0.52, body extent -0.55,-0.3 0.55,0.3, height 0.6
0402L [mm] "0402 from SM-752 data"
  rect 0.6x0.5 smd: 1(-0.5,0) 2(0.5,0)
  body extent -0.55,-0.3 0.55,0.3, height 0.6
0603 [mm] "0603 from SM-752 data"
  rect 1x0.95 smd: 1(-0.8,0) 2(0.8,0)
  silkscreen extent -1.52,-0.69 1.52,0.69, body extent -0.87,-0.47 0.87,0.47, height 1
0805_HV [mil] "0805 with 30mil clearance between pads"
  rect 50x63 smd: 1(-40,0) 2(40,0)
  silkscreen extent -74,-40 74,40, body extent -43,-29 43,29, height 57
1210_280 [mm] "SMD, 2-Leads, Body 3.6x2.8mm, Height 2.8mm"
  rect 1.1x2.2 smd: 1(-1.65,0) 2(1.65,0)
  silkscreen extent -0.84,-1.4 0.84,1.4, body extent -1.8,-1.4 1.8,1.4, height 2.8
1808 [mm] "Chip Capacitor, Body 4.6x2.0mm, IPC Medium Density"
  rect 1.4x2.3 smd: 1(-2.1,0) 2(2.1,0)
  silkscreen extent -3.1,-1.45 3.1,1.45, body extent -2.47,-1.2 2.47,1.2, height 2.03
1812_254 [mm] "SMD, 2-Leads, Body 4.8x3.4mm"
  rect 1.6x3.4 smd: 1(-2,0) 2(2,0)
  silkscreen extent -0.8,-1.7 0.8,1.7, body extent -2.4,-1.7 2.4,1.7, height 2.54
2010 [mm] "Chip Capacitor, Body 5.08x2.54mm, IPC Medium Density"
  rect 1.6x2.7 smd: 1(-2.3,0) 2(2.3,0)
  silkscreen extent -3.42,-1.65 3.42,1.65, body extent -2.73,-1.45 2.73,1.45, height 1.66
7343-31 [mm] "Medium Density based on Kemet T495 dimensions"
  rect 2.55x2.45 smd: 1(-3.025,0) 2(3.025,0)
  silkscreen extent -4.56,-2.3 3.8,2.3, body extent -3.8,-2.3 3.8,2.3, height 3.1
AssemblyNote [mil] "Assembly Note"
AssemblyNoteLabel [mil] "Assembly Note for PCB Labels"
CE_Mark_5mm [mil] "Minimum text height for CE Mark"
  silkscreen extent -138,-98 138,98
CONN_PEC03SAAN [mm] "SULLINS"
  rect 1.5x1.5 hole 1.016: 1(-2.54,0)
  round 1.5 hole 1.016: 2(0,0) 3(2.54,0)
  silkscreen extent -4.72,-1.27 3.81,1.27, body extent -3.84,-1.3 3.84,1.3, height 8.38
D0008A_N [mm] "SOIC, 8-Leads, Body 4.9x3.9mm, Pitch 1.27mm, IPC Medium Density"
  oval 1.45x0.6 smd: 1(-2.725,1.905) 2(-2.725,0.635) 3(-2.725,-0.635) 4(-2.725,-1.905) 5(2.725,-1.905) 6(2.725,-0.635) 7(2.725,0.635) 8(2.725,1.905)
  silkscreen extent -3.3,-2.5 0.9,2.5, body extent -3,-2.45 3,2.45, height 1.63
DQA0010A [mm] "SON, 10-Leads, Body 1x2.5mm, Pitch 0.5mm, TI Recommended"
  rrect50% 0.565x0.2 smd: 1(-0.417,1) 2(-0.417,0.5) 4(-0.417,-0.5) 5(-0.417,-1) 6(0.417,-1) 7(0.417,-0.5) 9(0.417,0.5) 10(0.417,1)
  rrect28% 0.565x0.36 on Top Paste: 3(-0.417,0) 8(0.417,0)
  rrect25% 0.565x0.4 smd paste-0.2: 3(-0.417,0) 8(0.417,0)
  silkscreen extent -0.67,-1.45 0.55,1.45, body extent -0.55,-1.3 0.55,1.3, height 0.56
ECS_ECS-33Q [mm] "SMD, 4-Leads, Body 2.5x3.2mm"
  rrect9% 1.1x1.3 smd: 1(-0.9,1.15) 2(-0.9,-1.15) 3(0.9,-1.15) 4(0.9,1.15)
  silkscreen extent -1.75,0.6 -1.75,1.7, body extent -1.3,-1.65 1.3,1.65, height 0.81
FCC_disclaimer [mil]
Fiducial10-20 [mm]
  round 1 smd mask+0.5: 1(0,0)
  Top Layer keep-out circle w1.178: c0,0 r0.5
Harwin_M7582-05 [mil] "Single Operation 2.54mm Pitch Open Top Jumper Socket"
  body extent -98,-47 98,47, height 236
HSMF-C165_RG [mm] "SMD, 4-Leads, Body 1.6x0.8mm"
  rect 0.7x0.4 smd: 1(-0.65,0.35) 2(-0.65,-0.35) 3(0.65,0.35) 4(0.65,-0.35)
  silkscreen extent -1,-0.8 1.5,0.8, body extent -0.85,-0.45 0.85,0.45, height 0.51
Keystone1502-2 [mm] "Double Turret"
  round 3.5 hole 2.5: 1(0,0)
  silkscreen extent -2.3,-2.3 2.3,2.3, body extent -1.6,-1.6 1.59,1.6, height 5.62
Keystone_1902C [mil] "Hex Standoff, 4-40 threaded, nylon"
  round 1 on Mech4: 0(0,0)
  body extent -145,-126 146,126, height 501
KSR [mm] "C&K Components SPST switch"
  rect 1.5x1.4 smd: 1(-3.25,0) 2(3.25,0)
  silkscreen extent -3.2,-2 3.2,2, body extent -3,-1.9 3,1.9, height 2.65
Label_650x200 [mil] "Thermal Transfer Label"
  round 1 on Mech14: 0(0,0)
  silkscreen extent -325,-100 325,100, body extent -325,-100 325,100, height 1
Molex_90122-0763 [mm] "Header, 2.54mm, 3x2, R/A, TH"
  rrect50% 1.5x1.5 hole 1: 1(-1.27,2.54)
  round 1.5 hole 1: 2(1.27,2.54) 3(-1.27,0) 4(1.27,0) 5(-1.27,-2.54) 6(1.27,-2.54)
  silkscreen extent -5.6,-3.9 -2.6,3.9, body extent -12.27,-3.81 1.57,3.81, height 6.35
Molex_0475890001 [mm] "Molex"
  rrect25% 0.4x1.35 smd: 1(-1.3,4.125) 2(-0.65,4.125) 3(0,4.125) 4(0.65,4.125) 5(1.3,4.125)
  oval 1.05x1.3 hole 0.7 slot 0.85 at 90 deg: 6(2.225,4.45) 11(-2.225,4.45)
  oval 0.8x2 hole 0.6 slot 1.3 at 90 deg: 7(4.175,1.45) 10(-4.175,1.45)
  rrect6% 1.8x2 smd: 8(1.15,1.45) 9(-1.15,1.45)
  Top Layer region: 2.6,0.45 2.6,2.45 4.175,2.45 4.175,0.45
  Top Layer region: -4.175,0.45 -4.175,2.45 -2.6,2.45 -2.6,0.45
  silkscreen extent -3.75,2.85 3.75,4.3, body extent -4.32,-1.3 4.33,4.59, height 2.81
Murata_CSTCR_G15L [mm] "Murata"
  rrect25% 0.4x2.6 smd: 1(-1.5,0) 2(0,0) 3(1.5,0)
  body extent -2.3,-1.05 2.3,1.05, height 1.2
"NY PMS 440 0025 PH" [mm] "4-40 nylon screw and mounting hole"
  round 8 hole 3.2: 1(0,0)
  body extent -3.3,-3.3 3.3,3.3, height 2.69
PN0080A_N [mm] "QFP, 80-Leads, Body 12x12mm, Pitch 0.5mm, IPC Medium Density"
  oval 1.45x0.3 smd: 1(-6.725,4.75) 2(-6.725,4.25) 3(-6.725,3.75) 4(-6.725,3.25) 5(-6.725,2.75) 6(-6.725,2.25) 7(-6.725,1.75) 8(-6.725,1.25) 9(-6.725,0.75) 10(-6.725,0.25) 11(-6.725,-0.25) 12(-6.725,-0.75) 13(-6.725,-1.25) 14(-6.725,-1.75) 15(-6.725,-2.25) 16(-6.725,-2.75) 17(-6.725,-3.25) 18(-6.725,-3.75) 19(-6.725,-4.25) 20(-6.725,-4.75) 41(6.725,-4.75) 42(6.725,-4.25) 43(6.725,-3.75) 44(6.725,-3.25) 45(6.725,-2.75) 46(6.725,-2.25) 47(6.725,-1.75) 48(6.725,-1.25) 49(6.725,-0.75) 50(6.725,-0.25) 51(6.725,0.25) 52(6.725,0.75) 53(6.725,1.25) 54(6.725,1.75) 55(6.725,2.25) 56(6.725,2.75) 57(6.725,3.25) 58(6.725,3.75) 59(6.725,4.25) 60(6.725,4.75)
  oval 0.3x1.45 smd: 21(-4.75,-6.725) 22(-4.25,-6.725) 23(-3.75,-6.725) 24(-3.25,-6.725) 25(-2.75,-6.725) 26(-2.25,-6.725) 27(-1.75,-6.725) 28(-1.25,-6.725) 29(-0.75,-6.725) 30(-0.25,-6.725) 31(0.25,-6.725) 32(0.75,-6.725) 33(1.25,-6.725) 34(1.75,-6.725) 35(2.25,-6.725) 36(2.75,-6.725) 37(3.25,-6.725) 38(3.75,-6.725) 39(4.25,-6.725) 40(4.75,-6.725) 61(4.75,6.725) 62(4.25,6.725) 63(3.75,6.725) 64(3.25,6.725) 65(2.75,6.725) 66(2.25,6.725) 67(1.75,6.725) 68(1.25,6.725) 69(0.75,6.725) 70(0.25,6.725) 71(-0.25,6.725) 72(-0.75,6.725) 73(-1.25,6.725) 74(-1.75,6.725) 75(-2.25,6.725) 76(-2.75,6.725) 77(-3.25,6.725) 78(-3.75,6.725) 79(-4.25,6.725) 80(-4.75,6.725)
  silkscreen extent -6.85,-5.6 5.6,5.6, body extent -7,-7 7,7, height 1.56
Pulse_HX1198FNLT [mm] "SMD, 16-Leads, Body 12.7x9.09mm, Pitch 1.27mm"
  rect 1.65x0.76 smd: 1(-4.255,4.445) 2(-4.255,3.175) 3(-4.255,1.905) 4(-4.255,0.635) 5(-4.255,-0.635) 6(-4.255,-1.905) 7(-4.255,-3.175) 8(-4.255,-4.445) 9(4.255,-4.445) 10(4.255,-3.175) 11(4.255,-1.905) 12(4.255,-0.635) 13(4.255,0.635) 14(4.255,1.905) 15(4.255,3.175) 16(4.255,4.445)
  silkscreen extent -4.86,-6.42 4.61,6.42, body extent -4.65,-6.42 4.65,6.42, height 6.13
QTLP630C_Green [mm] "SMT, 2-Leads, Body 2x1.25mm"
  rect 1.2x1.2 smd: 1(-1.05,0) 2(1.05,0)
  silkscreen extent -0.15,-0.8 2.15,0.8, body extent -1.1,-0.73 1.1,0.73, height 1.22
RMQ0024A [mm] "WQFN-24"
  rrect50% 0.45x0.2 smd: 1(-1.475,0.9) 2(-1.475,0.5) 4(-1.475,-0.5) 5(-1.475,-0.9) 13(1.475,-0.9) 14(1.475,-0.5) 16(1.475,0.5) 17(1.475,0.9)
  rrect25% 0.45x0.4 smd: 3(-1.475,0) 15(1.475,0)
  rrect40% 0.25x0.25 smd: 6(-1.325,-1.325) 12(1.325,-1.325) 18(1.325,1.325) 24(-1.325,1.325)
  rrect50% 0.2x0.45 smd: 7(-0.9,-1.475) 8(-0.5,-1.475) 10(0.5,-1.475) 11(0.9,-1.475) 19(0.9,1.475) 20(0.5,1.475) 22(-0.5,1.475) 23(-0.9,1.475)
  rrect25% 0.4x0.45 smd: 9(0,-1.475) 21(0,1.475)
  rrect5% 1.9x1.9 smd paste-1.9: 25(0,0)
  body extent -1.55,-1.55 1.55,1.55, height 0.81
Samtec_HTSW-102-07-G-S [mm] "Samtec 100mil, 1x2, 230 mil above insulator"
  rrect6% 1.65x1.65 hole 1.016: 1(-1.27,0)
  round 1.65 hole 1.016: 2(1.27,0)
  silkscreen extent -3.3,-1.27 2.54,1.27, body extent -2.54,-1.27 2.54,1.27, height 8.38
Samtec_HTSW-103-07-G-S [mm] "Samtec 100mil, 1x3, 230 mil above insulator"
  rrect6% 1.65x1.65 hole 1.016: 1(-2.54,0)
  round 1.65 hole 1.016: 2(0,0) 3(2.54,0)
  silkscreen extent -4.57,-1.27 3.81,1.27, body extent -3.81,-1.27 3.81,1.27, height 8.38
SMA [mm] "Molded Diode, 2-Leads, Body 4.3x2.6mm, IPC Medium Density, based on OnSemi component dimensions and land pattern"
  rect 2x2 smd: 1(-2,0) 2(2,0)
  silkscreen extent -3.66,-1.57 2.79,1.57, body extent -2.6,-1.3 2.6,1.3, height 2.42
Stewart_SS-7188S-A-NF [mm] "RJ-45, 1.27mm, R/A, TH"
  rrect50% 1.4x1.4 hole 0.89: 1(-4.445,6.35)
  round 1.4 hole 0.89: 2(-3.175,8.89) 3(-1.905,6.35) 4(-0.635,8.89) 5(0.635,6.35) 6(1.905,8.89) 7(3.175,6.35) 8(4.445,8.89)
  round 2.1 hole 1.57: S1(-7.745,3.05) S2(7.745,3.05)
  round 1.524 hole 3.215 unplated: ""(-5.715,0) ""(5.715,0)
  silkscreen extent -8.4,-10.79 8.07,10.8, body extent -8.06,-10.79 8.07,10.8, height 13.97
Sullins_xxxC010DAAN [mm] "Header, 2.54mm, 10x2, TH"
  rect 1.5x1.5 hole 1: 1(-1.27,11.43)
  round 1.5 hole 1: 2(1.27,11.43) 3(-1.27,8.89) 4(1.27,8.89) 5(-1.27,6.35) 6(1.27,6.35) 7(-1.27,3.81) 8(1.27,3.81) 9(-1.27,1.27) 10(1.27,1.27) 11(-1.27,-1.27) 12(1.27,-1.27) 13(-1.27,-3.81) 14(1.27,-3.81) 15(-1.27,-6.35) 16(1.27,-6.35) 17(-1.27,-8.89) 18(1.27,-8.89) 19(-1.27,-11.43) 20(1.27,-11.43)
  silkscreen extent -2.5,-12.7 2.5,13.14, body extent -2.5,-12.7 2.5,12.7, height 8.34
TDK_ACM9070 [mm] "SMD, 4-Leads, Body 9x7mm"
  rrect7% 2.5x1.5 smd: 1(-4.25,1.75) 2(-4.25,-1.75) 3(4.25,-1.75) 4(4.25,1.75)
  silkscreen extent -4.77,-3.6 4.6,3.6, body extent -4.6,-3.6 4.6,3.6, height 4.5
TE_5-146254-3 [mm] "TE 100mil, 3x2"
  rrect50% 1.65x1.65 hole 1.016: 1(-2.54,-1.27)
  round 1.65 hole 1.016: 2(-2.54,1.27) 3(0,-1.27) 4(0,1.27) 5(2.54,-1.27) 6(2.54,1.27)
  silkscreen extent -4.33,-2.44 3.61,2.44, body extent -3.61,-2.44 3.61,2.44, height 8.14
TE_5-1814400-1 [mm] "SMA Jack, 50 Ohm, R/A, TH"
  rrect50% 2x2 hole 1.5: 1(0,0)
  round 2.1 hole 1.6: 2(-2.54,2.54) 3(2.54,2.54) 4(2.54,-2.54) 5(-2.54,-2.54)
  silkscreen extent -3.15,-3.15 3.15,3.15, body extent -11.05,-3.16 3.15,3.16, height 10.43
TE_5-1814832-1 [mm] "SMA Straight PCB Socket Die Cast, TH"
  round 2 hole 1.5: 1(0,0)
  round 2.1 hole 1.6: 2(-2.54,2.54) 3(-2.54,-2.54) 4(2.54,-2.54) 5(2.54,2.54)
  silkscreen extent -3.2,-3.2 3.2,3.2, body extent -3.2,-3.2 3.2,3.2, height 9.5
TI_Stacked_Overlay_Small [mil]
  silkscreen extent -418,-98 418,98
TSW-102-07-G-D [mm] "Samtec 100mil, 2x2, 230 mil above insulator"
  rrect6% 1.65x1.65 hole 1.016: 1(-1.27,-1.27)
  round 1.65 hole 1.016: 2(-1.27,1.27) 3(1.27,-1.27) 4(1.27,1.27)
  silkscreen extent -3.56,-2.54 2.54,2.54, body extent -2.54,-2.54 2.54,2.54, height 8.38
WEEE_Minimum [mil] "WEEElie bin"
  silkscreen extent -95,-172 99,104

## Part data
C1: library part CMP-0011708-2, "CAP, TA, 4.7 uF, 35 V, +/- 10%, 1.3 ohm, SMD", Cap_Case=D, Manufacturer=Vishay-Sprague, Supplier Part Number 1=718-1084-1-ND, Tolerance_%=10%, Value1="1.3 ohm", Value2=35V, ValueDisplayed=4.7uF
C2 C36 C37 C38: library part CMP-0006641-2, "CAP, CERM, 0.1 uF, 16 V, +/- 10%, X7R, 0402", Cap_Case=0402, Manufacturer=MuRata, Supplier Part Number 1=490-3261-1-ND, TempCo=X7R, Tolerance_%=10%, Value1=Unknown, Value2=16V, ValueDisplayed=0.1uF
C3: library part CMP-0006620-2, "CAP, CERM, 1 uF, 35 V, +/- 20%, X5R, 0402", Cap_Case=0402, Manufacturer=MuRata, Supplier Part Number 1=490-10020-1-ND, TempCo=X5R, Tolerance_%=20%, Value1=Unknown, Value2=35V, ValueDisplayed=1uF
C4 C7: library part CMP-0007355-5, "CAP, CERM, 10 uF, 35 V, +/- 20%, X5R, 0603", Cap_Case=0603, Manufacturer=Nichicon, TempCo=X5R, Tolerance_%=20%, Value1=Unknown, Value2=35V, ValueDisplayed=10uF
C5 C6: library part CMP-0006526-2, "CAP, CERM, 2.2 uF, 16 V, +/- 10%, X6S, 0402", Cap_Case=0402, Manufacturer=MuRata, Supplier Part Number 1=GRM155C81C225KE11D-ND, TempCo=X6S, Tolerance_%=10%, Value1=Unknown, Value2=16V, ValueDisplayed=2.2uF
C8: library part CMP-0006389-2, "CAP, CERM, 470 pF, 25 V, +/- 5%, C0G/NP0, 0402", Cap_Case=0402, Manufacturer=MuRata, Supplier Part Number 1=GRM1555C1E471JA01D-ND, TempCo=C0G/NP0, Tolerance_%=5%, Value1=Unknown, Value2=25V, ValueDisplayed=470pF
C9: library part CMP-0009154-2, "CAP, CERM, 22 uF, 16 V, +/- 20%, X7R, AEC-Q200 Grade 1, 1210", Cap_Case=1210_280, Manufacturer=TDK, Supplier Part Number 1=445-5723-1-ND, TempCo=X7R, Tolerance_%=20%, Value1="0.002582 ohm", Value2=16V, ValueDisplayed=22uF
C10: library part CMP-0009155-2, "CAP, CERM, 10 uF, 25 V, +/- 20%, X7R, AEC-Q200 Grade 1, 1210", Cap_Case=1210, Manufacturer=TDK, Supplier Part Number 1=445-5720-1-ND, TempCo=X7R, Tolerance_%=20%, Value1=Unknown, Value2=25V, ValueDisplayed=10uF
C11 C12 C21 C22: library part CMP-0006862-5, "CAP, CERM, 0.1 uF, 10 V, +/- 10%, X7R, 0603", Cap_Case=0603, Manufacturer=Kemet, Supplier Part Number 1=399-1095-1-ND, TempCo=X7R, Tolerance_%=10%, Value1=Unknown, Value2=10V, ValueDisplayed=0.1uF
C13 C15: library part CMP-0006259-2, "CAP, CERM, 0.1 uF, 10 V, +/- 10%, X5R, 0402", Cap_Case=0402, Manufacturer=TDK, Supplier Part Number 1=445-1265-1-ND, TempCo=X5R, Tolerance_%=10%, Value1=Unknown, Value2=10V, ValueDisplayed=0.1uF
C14 C16: library part CMP-0006533-2, "CAP, CERM, 10 uF, 6.3 V, +/- 20%, X5R, 0402", Cap_Case=0402, Manufacturer=MuRata, TempCo=X5R, Tolerance_%=20%, Value1=Unknown, Value2=6.3V, ValueDisplayed=10uF
C17 C18 C19 C20: library part CMP-0006563-2, "CAP, CERM, 1 uF, 10 V, +/- 10%, X5R, 0402", Cap_Case=0402, Manufacturer=MuRata, Supplier Part Number 1=490-3890-1-ND, TempCo=X5R, Tolerance_%=10%, Value1=Unknown, Value2=10V, ValueDisplayed=1uF
C23: library part CMP-0006674-2, "CAP, CERM, 0.01 uF, 50 V, +/- 10%, X7R, 0402", Cap_Case=0402, Manufacturer=MuRata, Supplier Part Number 1=490-4516-1-ND, TempCo=X7R, Tolerance_%=10%, Value1=Unknown, Value2=50V, ValueDisplayed=0.01uF
C24 C25: library part CMP-0009436-2, "CAP, CERM, 1000 pF, 2000 V, +/- 10%, X7R, 1808", Cap_Case=1808, Manufacturer=MuRata, Supplier Part Number 1=490-8145-1-ND, TempCo=X7R, Tolerance_%=10%, Value1=Unknown, Value2=2000V, ValueDisplayed=1000pF
C26 C29: library part CMP-0007071-4, "CAP, CERM, 22 pF, 50 V, +/- 5%, C0G/NP0, AEC-Q200 Grade 1, 0603", Cap_Case=0603, Manufacturer=TDK, Supplier Part Number 1=445-5632-1-ND, TempCo=C0G/NP0, Tolerance_%=5%, Value1=Unknown, Value2=50V, ValueDisplayed=22pF
C27 C28: library part CMP-0009295-2, "CAP, CERM, 4700 pF, 2000 V, +/- 10%, X7R, 1812", Cap_Case=1812, Manufacturer=AVX, Supplier Part Number 1=478-3003-1-ND, TempCo=X7R, Tolerance_%=10%, Value1=Unknown, Value2=2000V, ValueDisplayed=4700pF
C30: library part CMP-0006254-2, "CAP, CERM, 1000 pF, 50 V, +/- 5%, C0G/NP0, 0402", Cap_Case=0402, Manufacturer=TDK, Supplier Part Number 1=445-13785-1-ND, TempCo=C0G/NP0, Tolerance_%=5%, Value1=Unknown, Value2=50V, ValueDisplayed=1000pF
C31 C34: library part CMP-0007013-5, "CAP, CERM, 0.22 uF, 50 V, +/- 10%, X5R, 0603", Cap_Case=0603, Manufacturer=TDK, Supplier Part Number 1=445-7460-1-ND, TempCo=X5R, Tolerance_%=10%, Value1="0.021699 ohm", Value2=50V, ValueDisplayed=0.22uF
C32: library part CMP-0007033-4, "CAP, CERM, 0.47 uF, 50 V, +/- 10%, X6S, 0603", Cap_Case=0603, Manufacturer=TDK, Supplier Part Number 1=445-7422-1-ND, TempCo=X6S, Tolerance_%=10%, Value1="0.010974 ohm", Value2=50V, ValueDisplayed=0.47uF
C33: library part CMP-0007022-5, "CAP, CERM, 4.7 uF, 35 V, +/- 10%, X5R, 0603", Cap_Case=0603, Manufacturer=TDK, Supplier Part Number 1=445-9064-1-ND, TempCo=X5R, Tolerance_%=10%, Value1="0.003728 ohm", Value2=35V, ValueDisplayed=4.7uF
C35: library part CMP-0011855-2, "CAP, TA, 10 uF, 35 V, +/- 10%, 0.125 ohm, SMD", Cap_Case=D, Manufacturer=AVX, Supplier Part Number 1=478-3337-1-ND, Tolerance_%=10%, Value1="0.125 ohm", Value2=35V, ValueDisplayed=10uF
C39 C40: library part CMP-0007074-4, "CAP, CERM, 10 pF, 50 V, +/- 5%, C0G/NP0, 0603", Cap_Case=0603, Manufacturer=TDK, Supplier Part Number 1=445-12387-1-ND, TempCo=C0G/NP0, Tolerance_%=5%, Value1=Unknown, Value2=50V, ValueDisplayed=10pF
D1: library part CMP-0028762-1, "Diode, Schottky, 60 V, 1 A, AEC-Q101, SMA", Manufacturer="ON Semiconductor", Supplier Part Number 1=NRVBA160T3G-ND, Value1=1A, Value2=0.51V
D2: library part CMP-0002934-2, "LED, Rg, SMD", Color=RG, Manufacturer=Avago, Supplier Part Number 1=516-1419-1-ND, Value1=W, Value2=2.2V
F1: library part CMP-0003588-3, "Fuse, 3 A, 32 VDC, SMD", Irating_A=3A, Manufacturer=AVX, Supplier Part Number 1=478-2868-1-ND
FID1 FID2 FID3 FID4 FID5 FID6: library part CMP-0077181-1, "Fiducial mark.  There is nothing to buy or mount.", Manufacturer=N/A
H1 H2 H3 H4: library part CMP-0003617-1, "Machine Screw, Round, #4-40 x 1/4, Nylon, Philips panhead", Manufacturer="B&F Fastener Supply", Supplier Part Number 1=H542-ND
H5 H6 H7 H8: library part CMP-0003610-1, "Standoff, Hex, 0.5\"L #4-40 Nylon", Manufacturer=Keystone, Supplier Part Number 1=36-1902C-ND
J1: library part CMP-0055301-1, "Connector, Receptacle, Micro-USB Type AB, R/A, Bottom Mount SMT", Manufacturer=Molex, Supplier Part Number 1=WM17143CT-ND
J2 J3 J4 J5: library part CMP-0002338-1, "Header, 100mil, 3x1, Tin, TH", Color=Black, Current_A=3A, Manufacturer="Sullins Connector Solutions", Supplier Part Number 1=S1012E-03-ND, Voltage_V=1.8kV
J6 J7: library part CMP-0055113-1, "Terminal, Turret, TH, Double", Manufacturer=Keystone, Supplier Part Number 1=36-1502-2-ND
J8: library part CMP-0054953-2, "Header, 100mil, 3x2, Tin, TH", Manufacturer="TE Connectivity"
J9: library part CMP-0054591-2, "Header, 2.54mm, 10x2, Gold, TH", Color=Black, Manufacturer="Sullins Connector Solutions", Supplier Part Number 1=S2011EC-10-ND
J10: library part CMP-0077741-2, "Header, 2.54mm, 3x2, Gold, R/A, TH", Color=Black, Current_A=3A, Manufacturer=Molex, Supplier Part Number 1=WM50030-06-ND, Voltage_V=350V
J11: library part CMP-0055866-1, "RJ45, 1.27mm, R/A, Gold, TH", Manufacturer="Stewart Connector", Supplier Part Number 1=380-1047-ND
J12: library part CMP-0054991-1, "JACK, SMA, 50 Ohm, Gold, R/A, TH", Manufacturer="TE Connectivity", Supplier Part Number 1=A97593-ND
J13: library part CMP-0075484-1, "Header, 100mil, 3x1, Gold, TH", Manufacturer=Samtec, Supplier Part Number 1=HTSW-103-07-G-S-ND
J14 J16 J17 J18: library part CMP-0075483-1, "Header, 100mil, 2x1, Gold, TH", Manufacturer=Samtec, Supplier Part Number 1=SAM8736-ND
J15: library part CMP-0054990-1, "SMA Straight PCB Socket Die Cast, 50 Ohm, TH", Manufacturer="TE Connectivity", Supplier Part Number 1=A97594-ND
J19: library part CMP-0075404-1, "Header, 100mil, 2x2, Gold, TH", Color=Black, Current_A=6.3A, Manufacturer=Samtec, Supplier Part Number 1=SAM1028-02-ND, Voltage_V=550V
L1: library part CMP-0003343-2, "Ferrite Bead, 1000 ohm @ 100 MHz, 0.4 A, 0603", Manufacturer=MuRata, Supplier Part Number 1=490-1015-1-ND, Value1="0.5 ohm", Value2=0.4A, ValueDisplayed="1000 ohm"
LBL1: library part CMP-0003625-1, "Thermal Transfer Printable Labels, 0.650\" W x 0.200\" H - 10,000 per roll", Manufacturer=Brady, Supplier Part Number 1=97C5133
LD1 LD2 LD3 LD4: library part CMP-0002917-1, "LED, Green, SMD", Color=Green, Manufacturer=Everlight, Supplier Part Number 1=1080-1411-1-ND, Value1=W, Value2=2.1V
Logo1: library part CMP-0074844-1
Logo2: library part CMP-0074838-1, "Texas Instrument Corporate Signature"
Logo3: library part CMP-0074847-1, "FCC_disclaimer"
Logo4: library part CMP-0074769-1
R1 R2 R5: library part CMP-0025874-4, "RES, 0, 5%, 0.1 W, AEC-Q200 Grade 0, 0603", Manufacturer=Panasonic, Power_W=100mW, Supplier Part Number 1=P0.0GCT-ND, TempCo="600 ppm/C", Tolerance_%=5%, Value2=0.1W, Value_Code=0000, ValueDisplayed=0
R3: library part CMP-0026768-2, "RES, 100 k, 0.5%, 0.063 W, AEC-Q200 Grade 0, 0402", Manufacturer=Vishay-Dale, Power_W=63mW, Supplier Part Number 1=541-100KAVCT-ND, TempCo="50 ppm/C", Tolerance_%=0.5%, Value2=0.063W, Value_Code=100k
R4 R28 R30 R32: library part CMP-0026934-3, "RES, 470, 5%, 0.063 W, AEC-Q200 Grade 0, 0402", Manufacturer=Vishay-Dale, Power_W=63mW, Supplier Part Number 1=541-470JCT-ND, TempCo="200 ppm/C", Tolerance_%=5%, Value2=0.063W, Value_Code=470R, ValueDisplayed=470
R6: library part CMP-0026036-3, "RES, 165 k, 1%, 0.063 W, AEC-Q200 Grade 0, 0402", Manufacturer=Vishay-Dale, Power_W=63mW, Supplier Part Number 1=541-165KLCT-ND, TempCo="100 ppm/C", Tolerance_%=1%, Value2=0.063W, Value_Code=165k
R7: library part CMP-0026908-3, "RES, 33, 5%, 0.063 W, AEC-Q200 Grade 0, 0402", Manufacturer=Vishay-Dale, Power_W=63mW, Supplier Part Number 1=541-33JCT-ND, TempCo="200 ppm/C", Tolerance_%=5%, Value2=0.063W, Value_Code=33R0, ValueDisplayed=33
R8: library part CMP-0027002-2, "RES, 0, 5%, 0.063 W, 0402", Manufacturer=Rohm, Power_W=63mW, Supplier Part Number 1=RHM0.0JCT-ND, TempCo="500 ppm/C", Tolerance_%=5%, Value2=0.063W, Value_Code=0000, ValueDisplayed=0
R9 R10 R11 R12 R13 R14 R15 R16 R17 R18 R19 R27 R48 R52: library part CMP-0026822-3, "RES, 0, 5%, 0.063 W, AEC-Q200 Grade 0, 0402", Manufacturer=Vishay-Dale, Power_W=63mW, Supplier Part Number 1=541-0.0JCT-ND, TempCo="200 ppm/C", Tolerance_%=5%, Value2=0.063W, Value_Code=0000, ValueDisplayed=0
R20: library part CMP-0026890-5, "RES, 2.2 k, 5%, 0.063 W, AEC-Q200 Grade 0, 0402", Manufacturer=Vishay-Dale, Power_W=63mW, Supplier Part Number 1=541-2.2KJCT-ND, TempCo="200 ppm/C", Tolerance_%=5%, Value2=0.063W, Value_Code=2k20, ValueDisplayed=2.2k
R21: library part CMP-0026515-2, "RES, 6.49 k, 1%, 0.063 W, AEC-Q200 Grade 0, 0402", Manufacturer=Vishay-Dale, Power_W=63mW, Supplier Part Number 1=541-6.49KLCT-ND, TempCo="100 ppm/C", Tolerance_%=1%, Value2=0.063W, Value_Code=6k49, ValueDisplayed=6.49k
R22: library part CMP-0027010-2, "RES, 2.2 k, 5%, 0.05 W, 0201", Manufacturer=Vishay-Dale, Power_W=50mW, Supplier Part Number 1=541-2.2KAGCT-ND, TempCo="200 ppm/C", Tolerance_%=5%, Value2=0.05W, Value_Code=2k20, ValueDisplayed=2.2k
R23 R24 R25 R26: library part CMP-0021425-3, "RES, 75.0, 1%, 0.125 W, AEC-Q200 Grade 0, 0805", Manufacturer=Vishay-Dale, Power_W=125mW, Supplier Part Number 1=541-75.0CCT-ND, TempCo="100 ppm/C", Tolerance_%=1%, Value2=0.125W, Value_Code=75R0, ValueDisplayed=75.0
R29 R31 R36 R39 R40 R42 R43: library part CMP-0026237-2, "RES, 2.49 k, 1%, 0.063 W, AEC-Q200 Grade 0, 0402", Manufacturer=Vishay-Dale, Power_W=63mW, Supplier Part Number 1=541-2.49KLCT-ND, TempCo="100 ppm/C", Tolerance_%=1%, Value2=0.063W, Value_Code=2k49, ValueDisplayed=2.49k
R33 R38 R41 R46 R47: library part CMP-0027011-4, "RES, 0, 5%, 0.05 W, AEC-Q200 Grade 1, 0201", Manufacturer=Panasonic, Power_W=50mW, Supplier Part Number 1=P0.0AGCT-ND, TempCo="600 ppm/C", Tolerance_%=5%, Value2=0.05W, Value_Code=0000, ValueDisplayed=0
R34 R35: library part CMP-0016535-2, "RES, 1.00 M, 1%, 1 W, 2010", Manufacturer="Stackpole Electronics Inc", Power_W=1W, Supplier Part Number 1=HVCB2010FKC1M00CT-ND, TempCo="50 ppm/C", Tolerance_%=1%, Value_Code=1M00, ValueDisplayed=1.00M
R37: library part CMP-0026727-1, "RES, 1.00 M, 1%, 0.063 W, 0402", Manufacturer="Yageo America", Power_W=63mW, Supplier Part Number 1=311-1.00MLRCT-ND, TempCo="100 ppm/C", Tolerance_%=1%, Value2=0.063W, Value_Code=1M00, ValueDisplayed=1.00M
R44 R45: library part CMP-0027127-1, "RES, 470, 5%, 0.05 W, 0201", Manufacturer="Yageo America", Power_W=50mW, Supplier Part Number 1=311-470NCT-ND, TempCo="200 ppm/C", Tolerance_%=5%, Value2=0.05W, Value_Code=470R, ValueDisplayed=470
R49: library part CMP-0026935-3, "RES, 47 k, 5%, 0.063 W, AEC-Q200 Grade 0, 0402", Manufacturer=Vishay-Dale, Power_W=63mW, Supplier Part Number 1=541-47KJCT-ND, TempCo="200 ppm/C", Tolerance_%=5%, Value2=0.063W, Value_Code=47k0, ValueDisplayed=47k
R50: library part CMP-0026085-3, "RES, 1.40 k, 1%, 0.063 W, AEC-Q200 Grade 0, 0402", Manufacturer=Vishay-Dale, Power_W=63mW, Supplier Part Number 1=541-1.40KLCT-ND, TempCo="100 ppm/C", Tolerance_%=1%, Value2=0.063W, Value_Code=1k40, ValueDisplayed=1.40k
R51: library part CMP-0026100-2, "RES, 1.00 M, 1%, 0.063 W, AEC-Q200 Grade 0, 0402", Manufacturer=Vishay-Dale, Power_W=63mW, Supplier Part Number 1=541-1.00MLCT-ND, TempCo="100 ppm/C", Tolerance_%=1%, Value2=0.063W, Value_Code=1M00, ValueDisplayed=1.00M
R53 R54: library part CMP-0026888-3, "RES, 27, 5%, 0.063 W, AEC-Q200 Grade 0, 0402", Manufacturer=Vishay-Dale, Power_W=63mW, Supplier Part Number 1=541-27JCT-ND, TempCo="200 ppm/C", Tolerance_%=5%, Value2=0.063W, Value_Code=27R0, ValueDisplayed=27
S1: library part CMP-0002170-2, "Switch, Normally open, 2.3N force, 200k operations, SMD", CurrentRating_mA=1.001kA, Manufacturer="C&K Components"
SH-J1 SH-J2 SH-J3 SH-J4 SH-J5: library part CMP-0078738-1, "Single Operation 2.54mm Pitch Open Top Jumper Socket", Manufacturer=Harwin, Supplier Part Number 1=952-2881-ND
T1: library part CMP-0013076-2, "Coupled inductor, 5 A, 0.01 ohm, SMD", Manufacturer=TDK, Supplier Part Number 1=445-2216-1-ND
T2: library part CMP-0030426-3, "Transformer, 350 uH, SMT", Manufacturer="Pulse Engineering", Supplier Part Number 1=553-2209-1-ND, ValueDisplayed=350uH
U1: library part CMP-0036447-1, "Single Output Low Noise LDO, 500 mA, Adjustable 1.3 to 6.5 V Output, 2.5 to 16 V Input, 8-pin SOIC (D), -40 to 125 degC, Green (RoHS & no Sb/Br)", Manufacturer="Texas Instruments", Rating=Catalog
U2: library part CMP-0073613-3, "4-Channel Ultra-Low-Capacitance IEC ESD Protection Diode, DQA0010A (USON-10)", Alternate Manufacturer="Texas Instruments"
U3: library part CMP-0084215-1, "DP83825IRMQR, RMQ0024A (WQFN-24)", Alternate Manufacturer="Texas Instruments", Alternate PartNumber=DP83825IRMQT
U4: library part CMP-0038965-1, "25 MHz Mixed Signal Microcontroller with 128 KB Flash, 8192 B SRAM and 63 GPIOs, -40 to 85 degC, 80-pin QFP (PN), Green (RoHS & no Sb/Br)", Frequency(MHz)=25, Manufacturer="Texas Instruments", Temp Sensor=Yes
XTAL1: library part CMP-0079863-1, "Crystal, 25 MHz, 20 ppm, AEC-Q200 Grade 1, SMD", Frequency_Fixed=25MHz, Frequency Stability="50 ppm", Frequency Tolerance="20 ppm", Manufacturer="ECS Inc.", Supplier Part Number 1=XC2151CT-ND
Y1: library part CMP-0006148-5, "Resonator, 4 MHz, 1000 ppm, 39 pF, SMD", Frequency_Fixed=4MHz, Frequency Stability="800 ppm", Frequency Tolerance="1000 ppm", Load Capacitance="39 pF", Manufacturer=MuRata, Supplier Part Number 1=490-7861-1-ND
ZZ1: library part CMP-0003616-3
ZZ2: library part CMP-0077236-1
ZZ3: library part CMP-0077237-1
ZZ4: library part CMP-0077238-1

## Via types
v1: diameter 24, hole 12, Top Layer to Bottom Layer, tented both sides, 337 vias
v2: diameter 19.68, hole 7.87, Top Layer to Bottom Layer, 5 vias
v3: diameter 24, hole 12, Top Layer to Bottom Layer, tented bottom, 1 vias

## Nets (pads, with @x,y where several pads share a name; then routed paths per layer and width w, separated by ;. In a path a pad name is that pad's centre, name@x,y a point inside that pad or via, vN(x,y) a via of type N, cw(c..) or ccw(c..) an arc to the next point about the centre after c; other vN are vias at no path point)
3V3_IO_LDO: J4.1 J5.1 L1.2 | length 1608.7
  Top Layer w25: L1.2@420,1461.5 708.5,1461.5 830,1340 930,1340 1240,1650 J5.1@1680,1650
  Bottom Layer w25: J5.1@1680,1650 J4.1@1850,1650
3V3_VDD_LDO: J3.1 R1.2 | length 1658.6
  Top Layer w25: R1.2@561.5,1397.22 640,1397.22 767.22,1270 960,1270 1260,1570 1930,1570 J3.1@2010,1650
5V-12V: C9.1 C10.1 D1.1 J2.3 R8.2 | length 553
  Bottom Layer w20: J2.3@660,970 ccw(c684.14,994.14) 684.14,960 R8.2@786.38,960
  Bottom Layer w25: C10.1@514.96,660 514.96,797.01 D1.1@638.27,797.01
  Bottom Layer w50: D1.1@651.26,810 651.26,961.26 J2.3@660,970
CLK_OUT: R27.1 R30.1 R36.1 U3.2 | length 1426.9
  Top Layer w8: U3.2@1450.31,931.93 1450.31,699.69 1630,520 1770,520 1836.38,453.62 R27.1@2348.19,453.62 cw(c2359.21,464.65) 2343.62,464.65 R30.1@2343.62,500 cw(c2424.79,500) v1(2367.4,557.4)
  Bottom Layer w8: R36.1@2300,596.38 2328.41,596.38 v1(2367.4,557.4)
CRS_DV: J18.1 R13.2 U3.20 | length 1251.1
  Top Layer w12: U3.20@1411.93,1009.69 1293.62,1009.69 1280,996.06 v1(1280,790) 1280,510 1360,430 1550,430 1610,370 R13.2@1610,313.62
  Bottom Layer w12: J18.1@1130,870 1210,790 v1(1280,790)
CRS_DV_S: J9.10 R13.1 | length 96.4
  Top Layer w12: J9.10@1610,170 R13.1@1610,266.38
EARTH_GND: C24.2 C25.2 C27.2 C28.2 H4.1 J11.S1 J11.S2 R34.1 R35.1
  other v1: 2828,66 2908,66 2988,66 3068,66 2868,146 2948,146 3028,146 2908,226 2988,226 2868,306 2948,306 3028,306 3348,306 2748,386 2828,386 2908,386 2988,386 3068,386 3148,386 3228,386 3308,386 2788,466 2868,466 2948,466 3028,466 3188,466 3268,466 3348,466 2748,546 2828,546 2908,546 2988,546 3228,546 3308,546 2788,626 2868,626 2948,626 3028,626 3108,626 3188,626 3268,626 3348,626 2748,706 2828,706 2908,706 2988,706 3068,706 3148,706 3228,706 3308,706 3028,786 3188,786 3268,786 3348,786 2988,866 3228,866 3308,866 3348,946 2668,1026 2748,1026 2988,1026 3148,1026 2628,1106 2708,1106 2788,1106 3188,1106 3268,1106 3348,1106 2508,1186 2908,1186 3068,1186 3148,1186 3228,1186 3308,1186 2628,1266 3108,1266 3188,1266 3268,1266 3348,1266 2748,1346 3068,1346 3148,1346 3308,1346 3028,1426 3108,1426 3348,1426 2588,1506 2668,1506 3308,1506
EXT_REF_CLK: J15.1 R41.1 | length 1226.3
  Bottom Layer w12: R41.1@1572.99,1080 2240,1747.01 J15.1@2240,2030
